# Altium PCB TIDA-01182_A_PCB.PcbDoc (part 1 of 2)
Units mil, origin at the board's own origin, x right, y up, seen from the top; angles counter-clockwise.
Board outline 4950 x 3200 mil, 4 copper layers (Component Side, Signal Layer 1, Signal Layer 2, Solder Side), stack 61.2 mil thick; 169 components, 99 nets, 868 pads, 44 vias.
Unrouted connection lines stored in the file: 4.
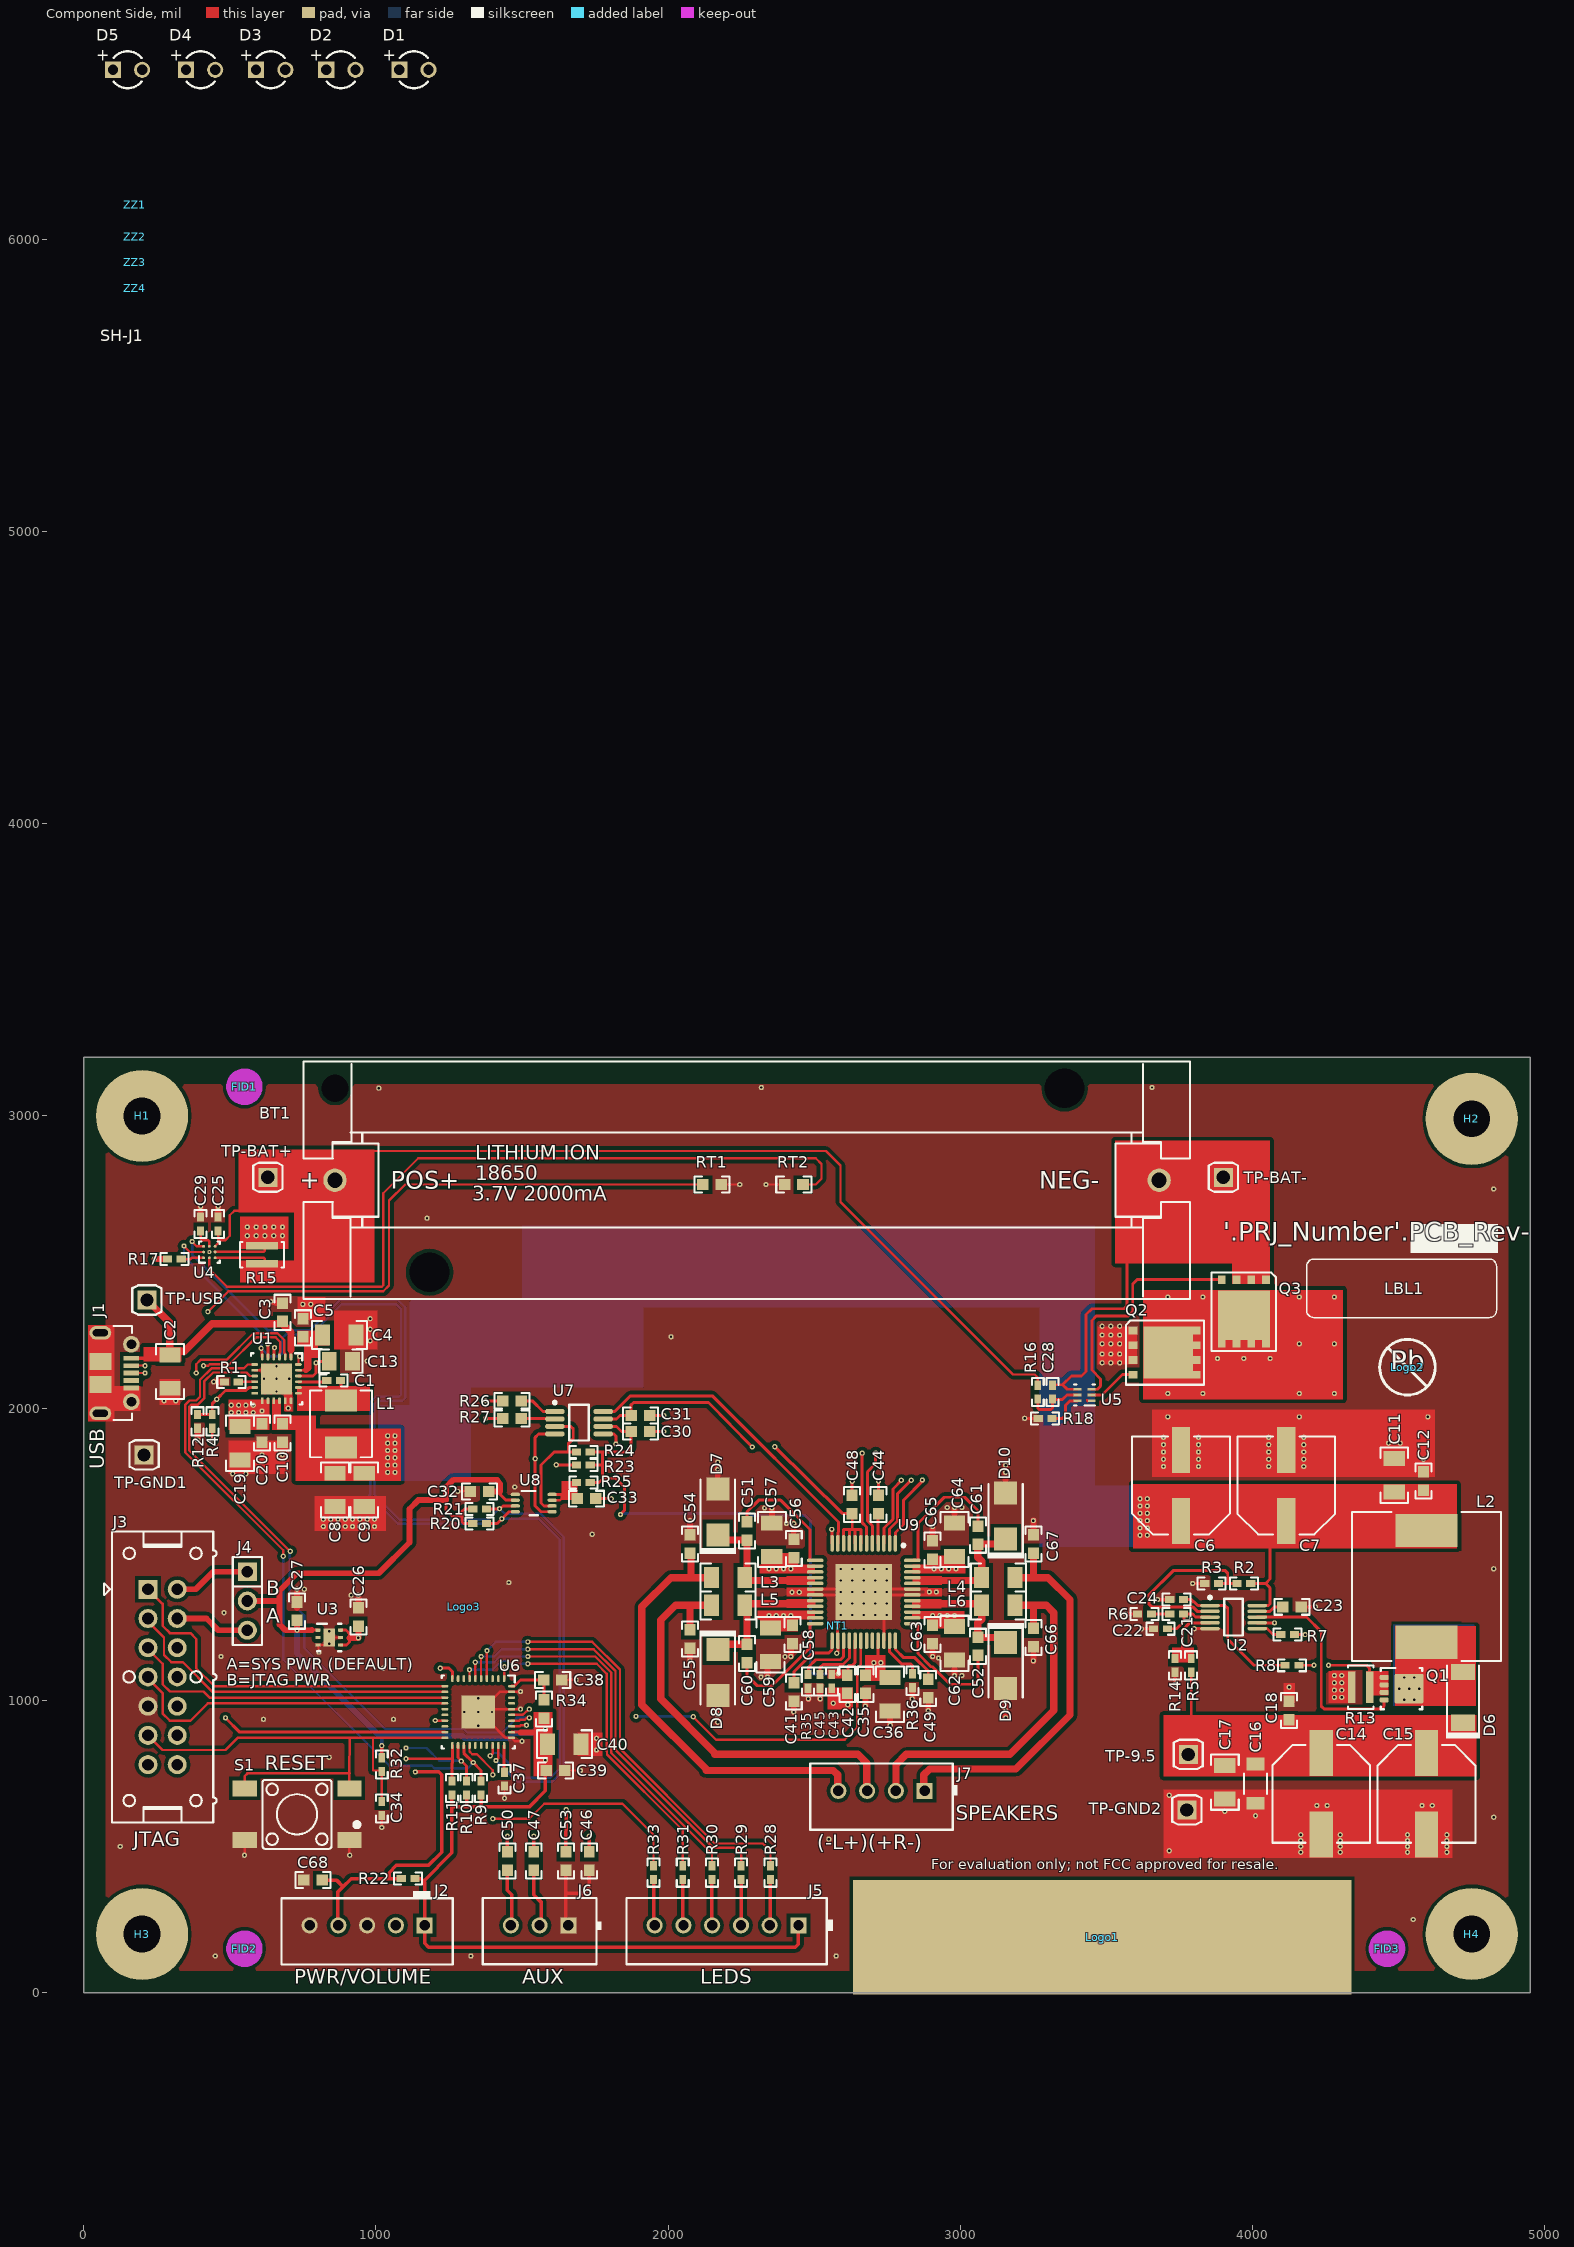
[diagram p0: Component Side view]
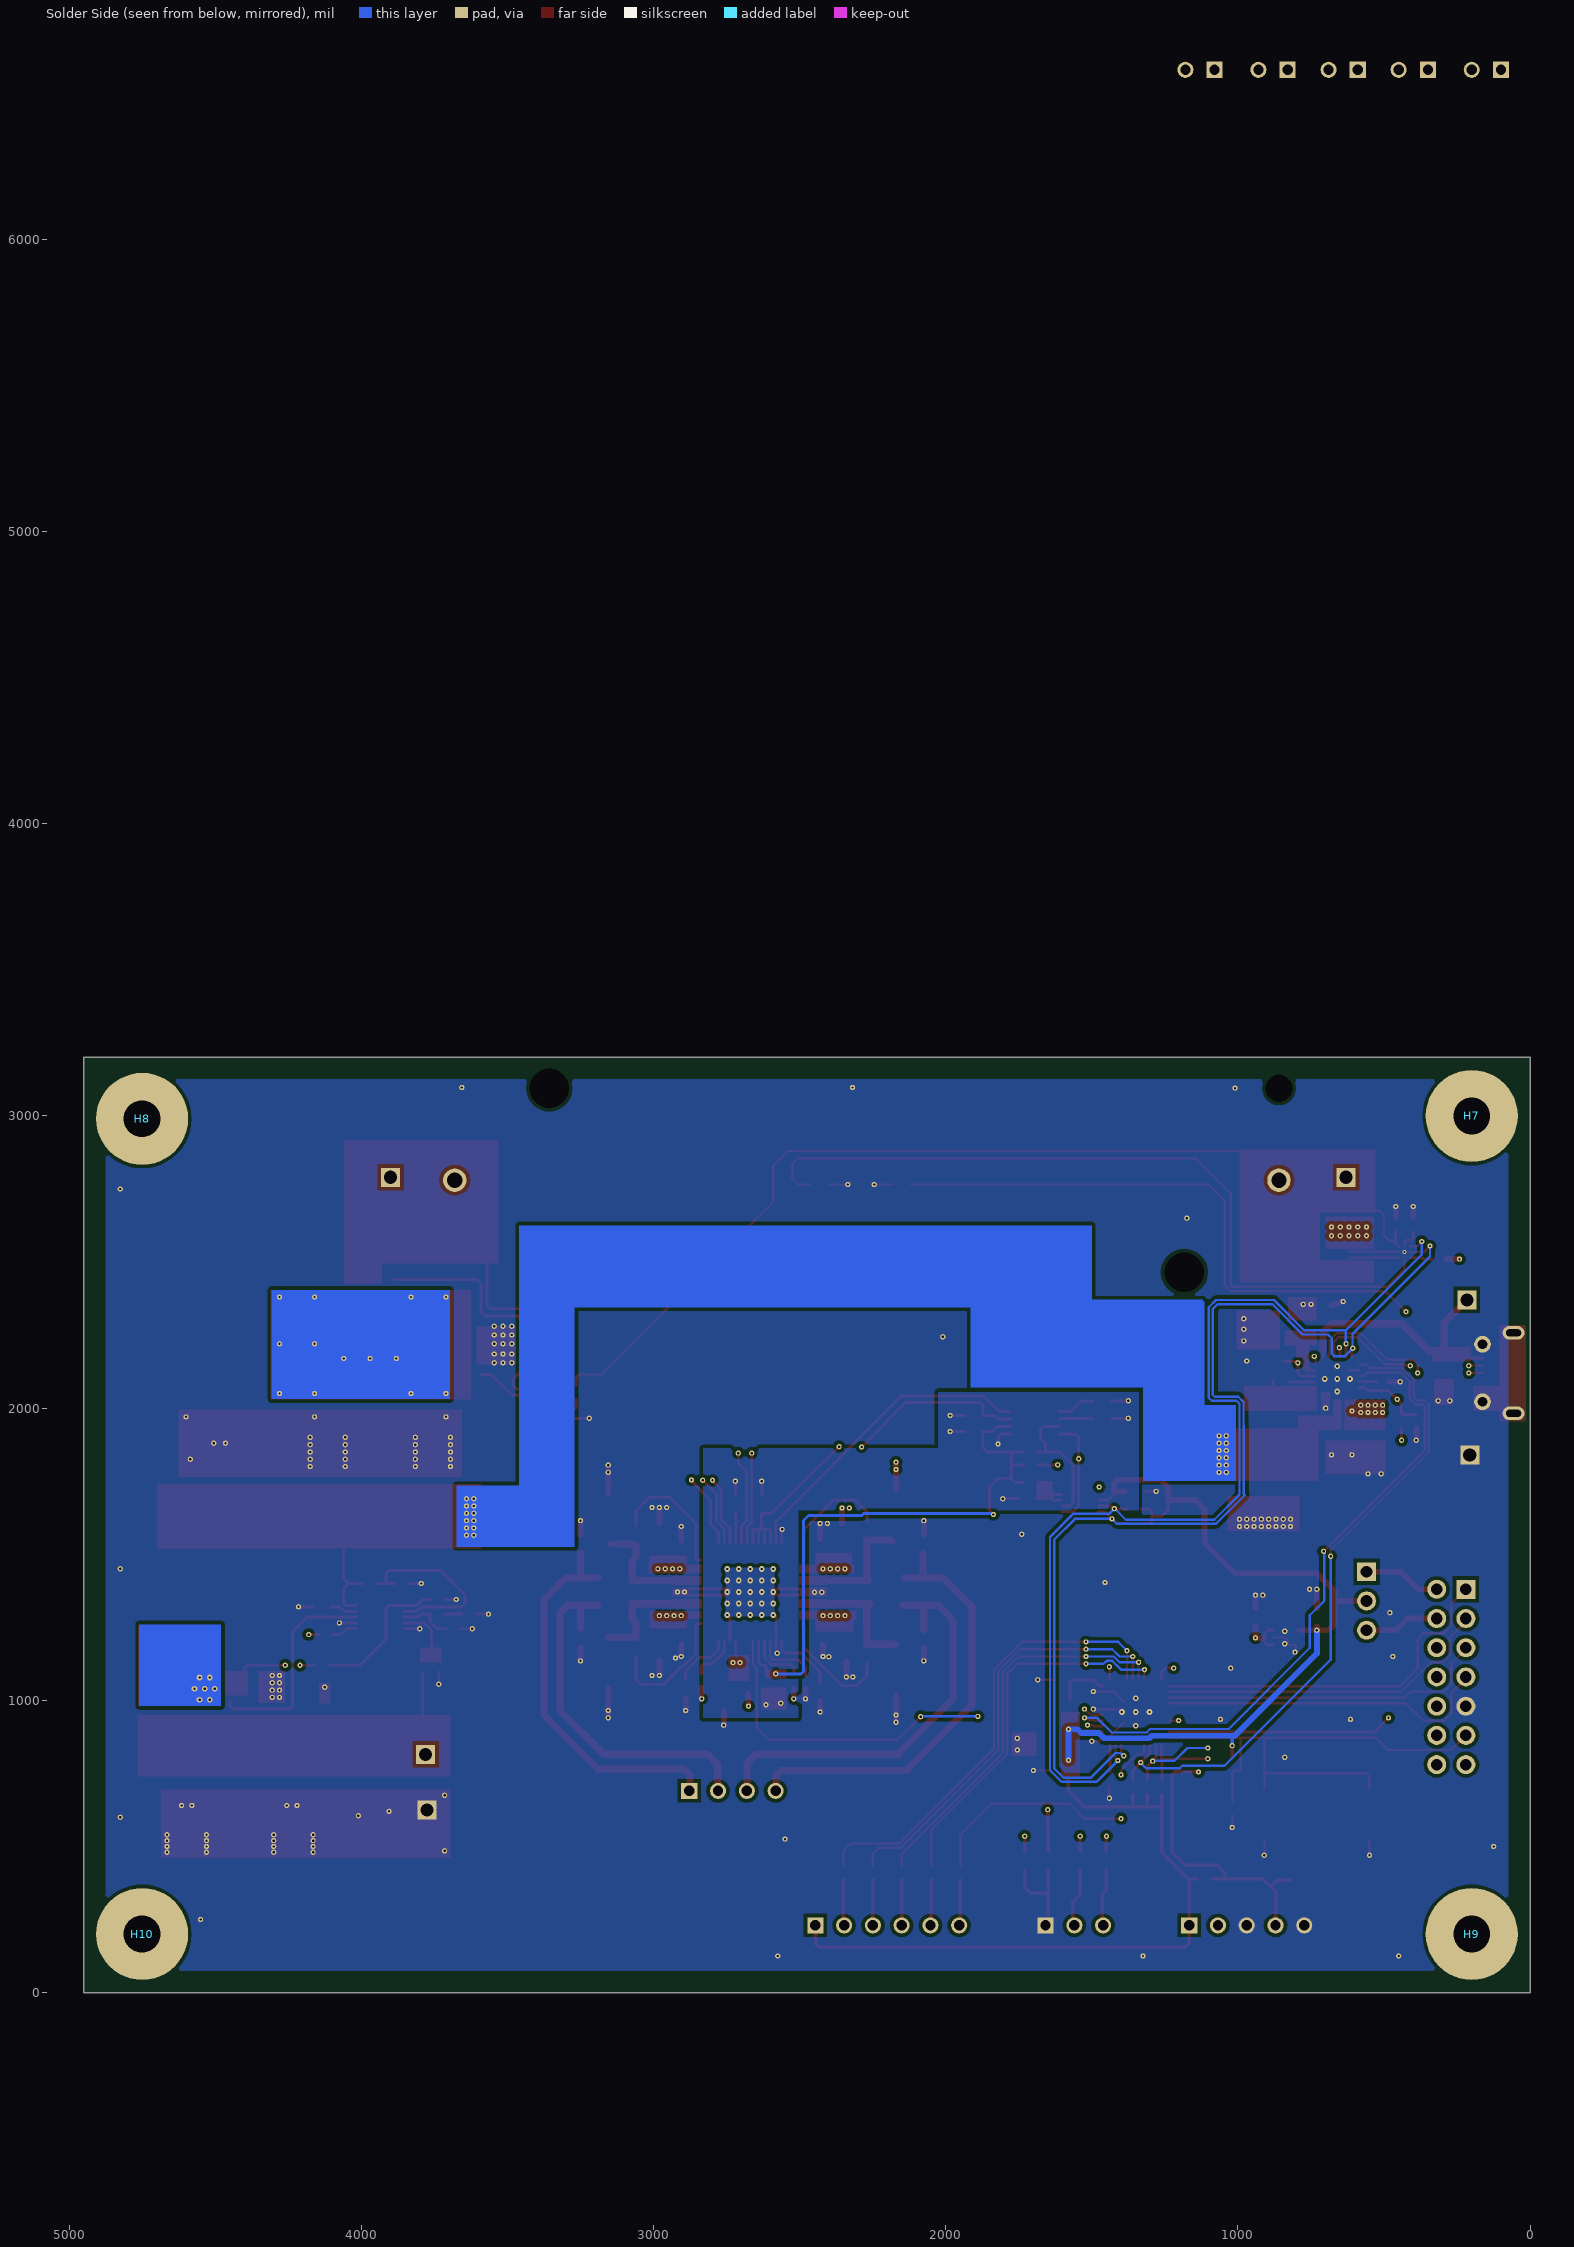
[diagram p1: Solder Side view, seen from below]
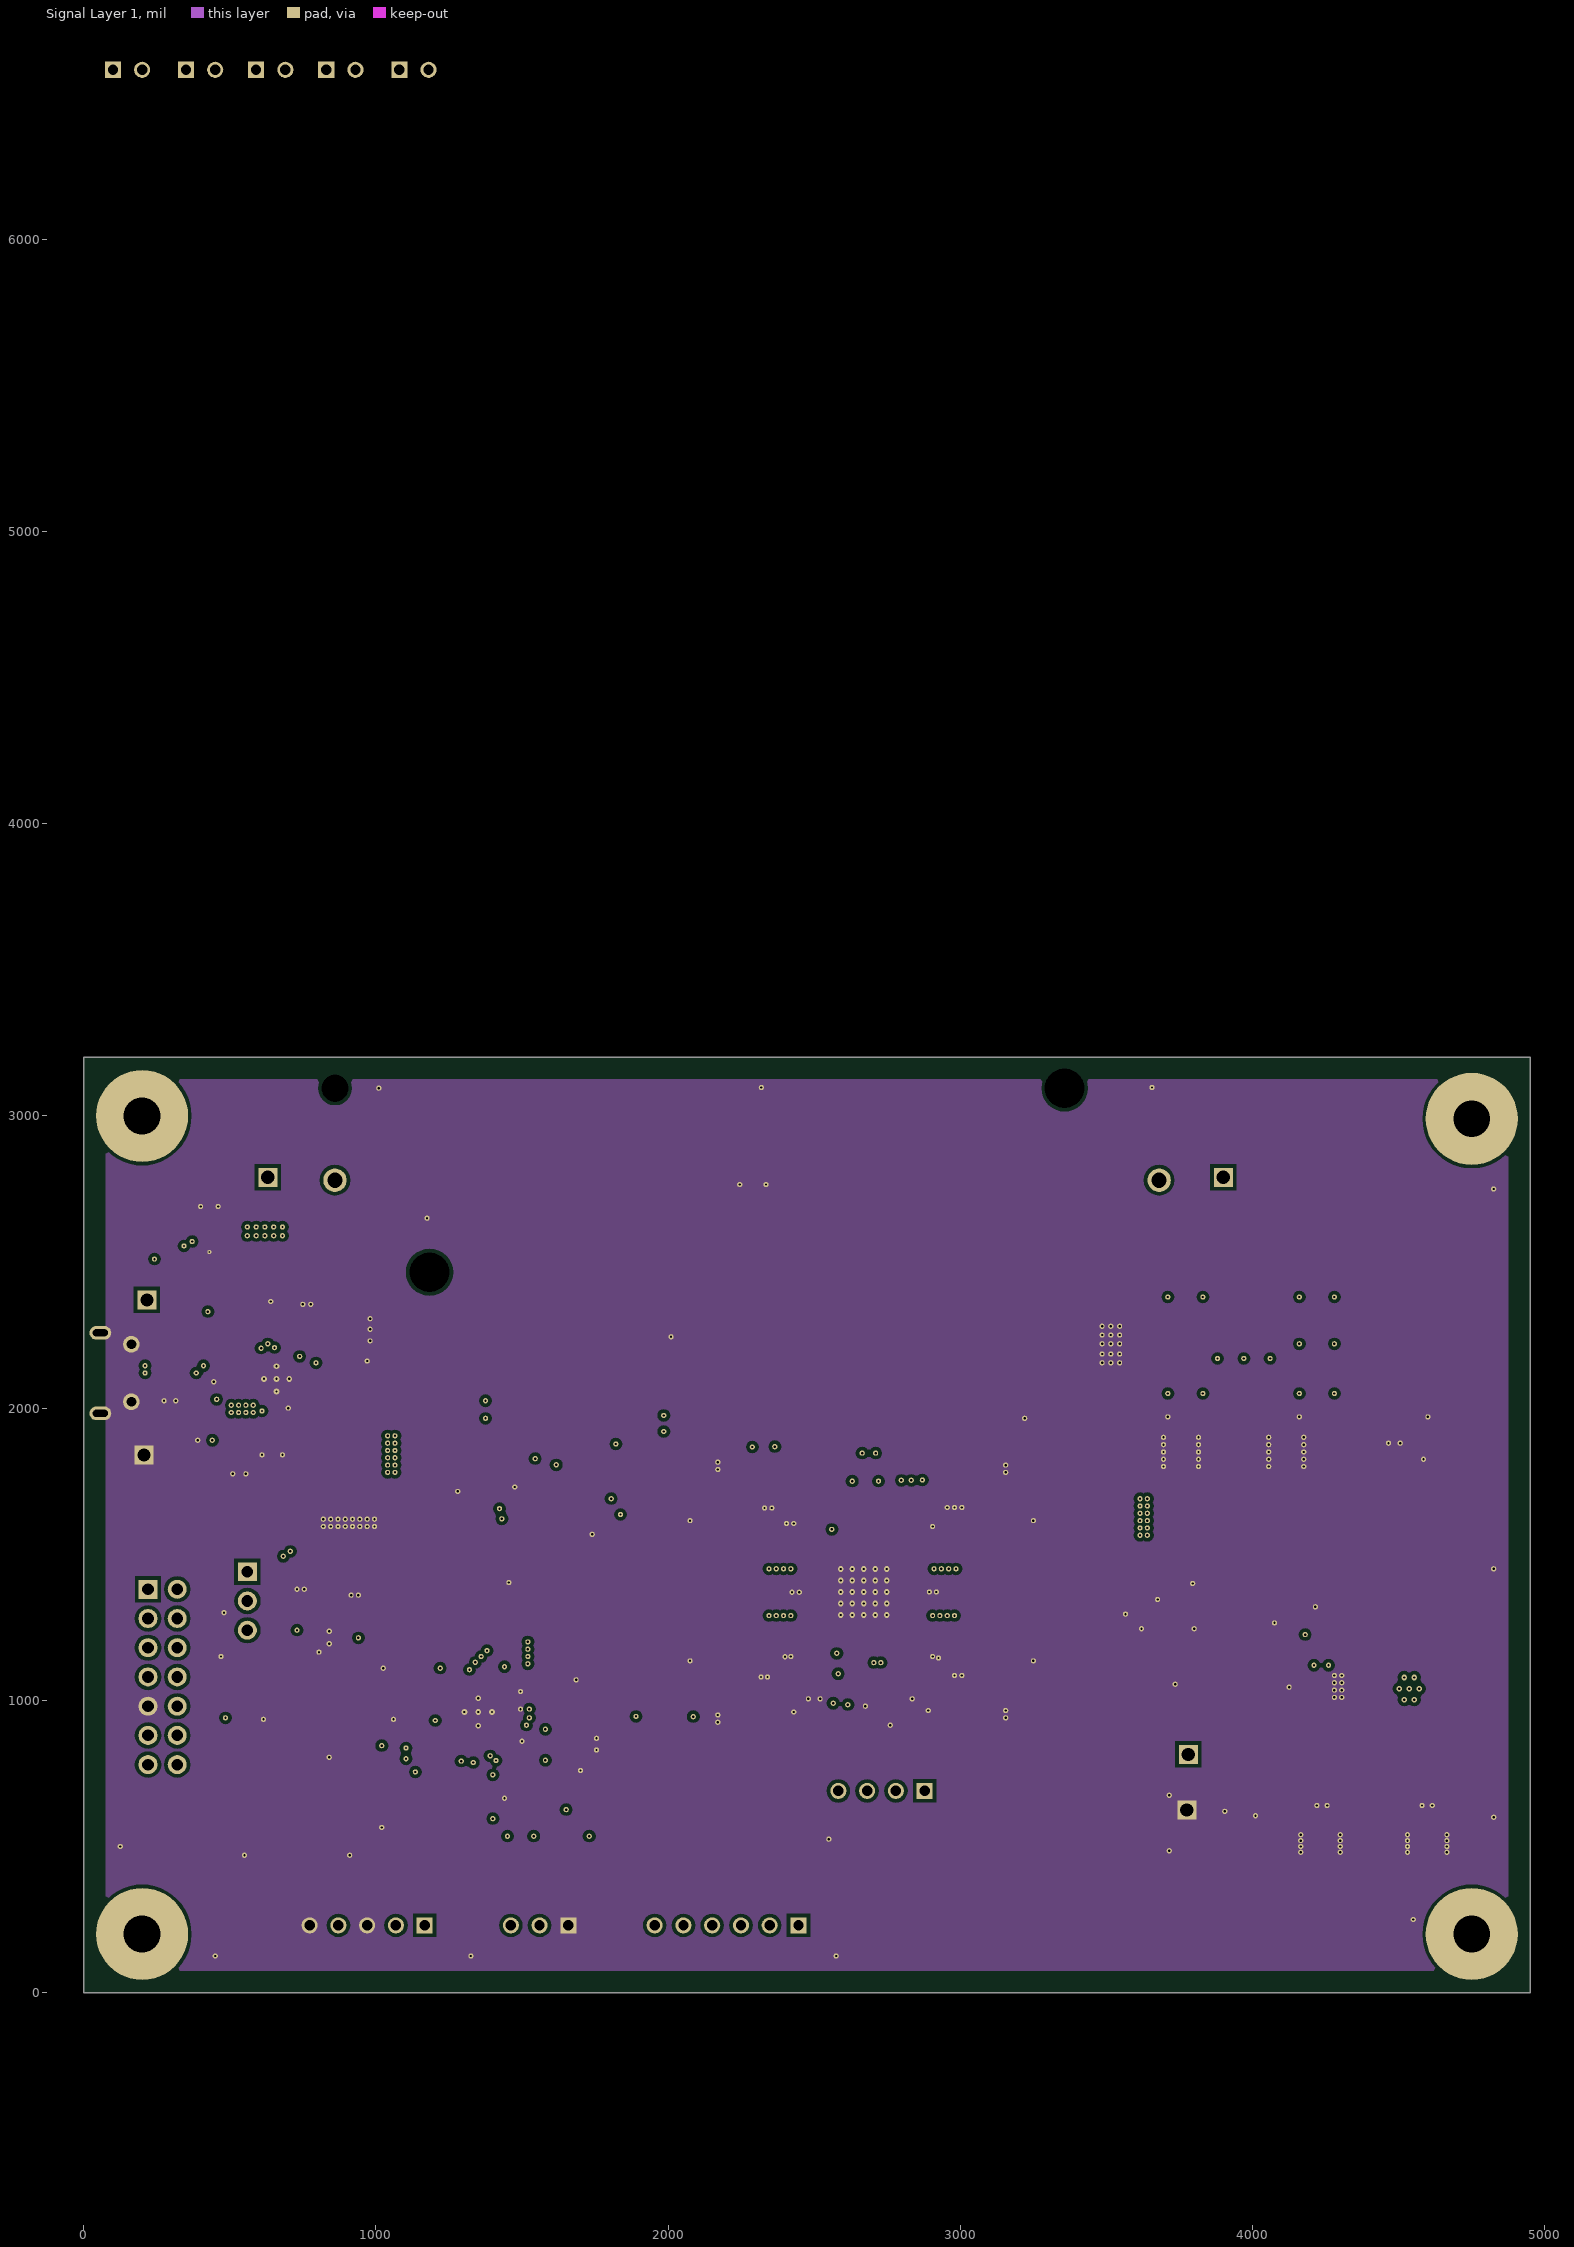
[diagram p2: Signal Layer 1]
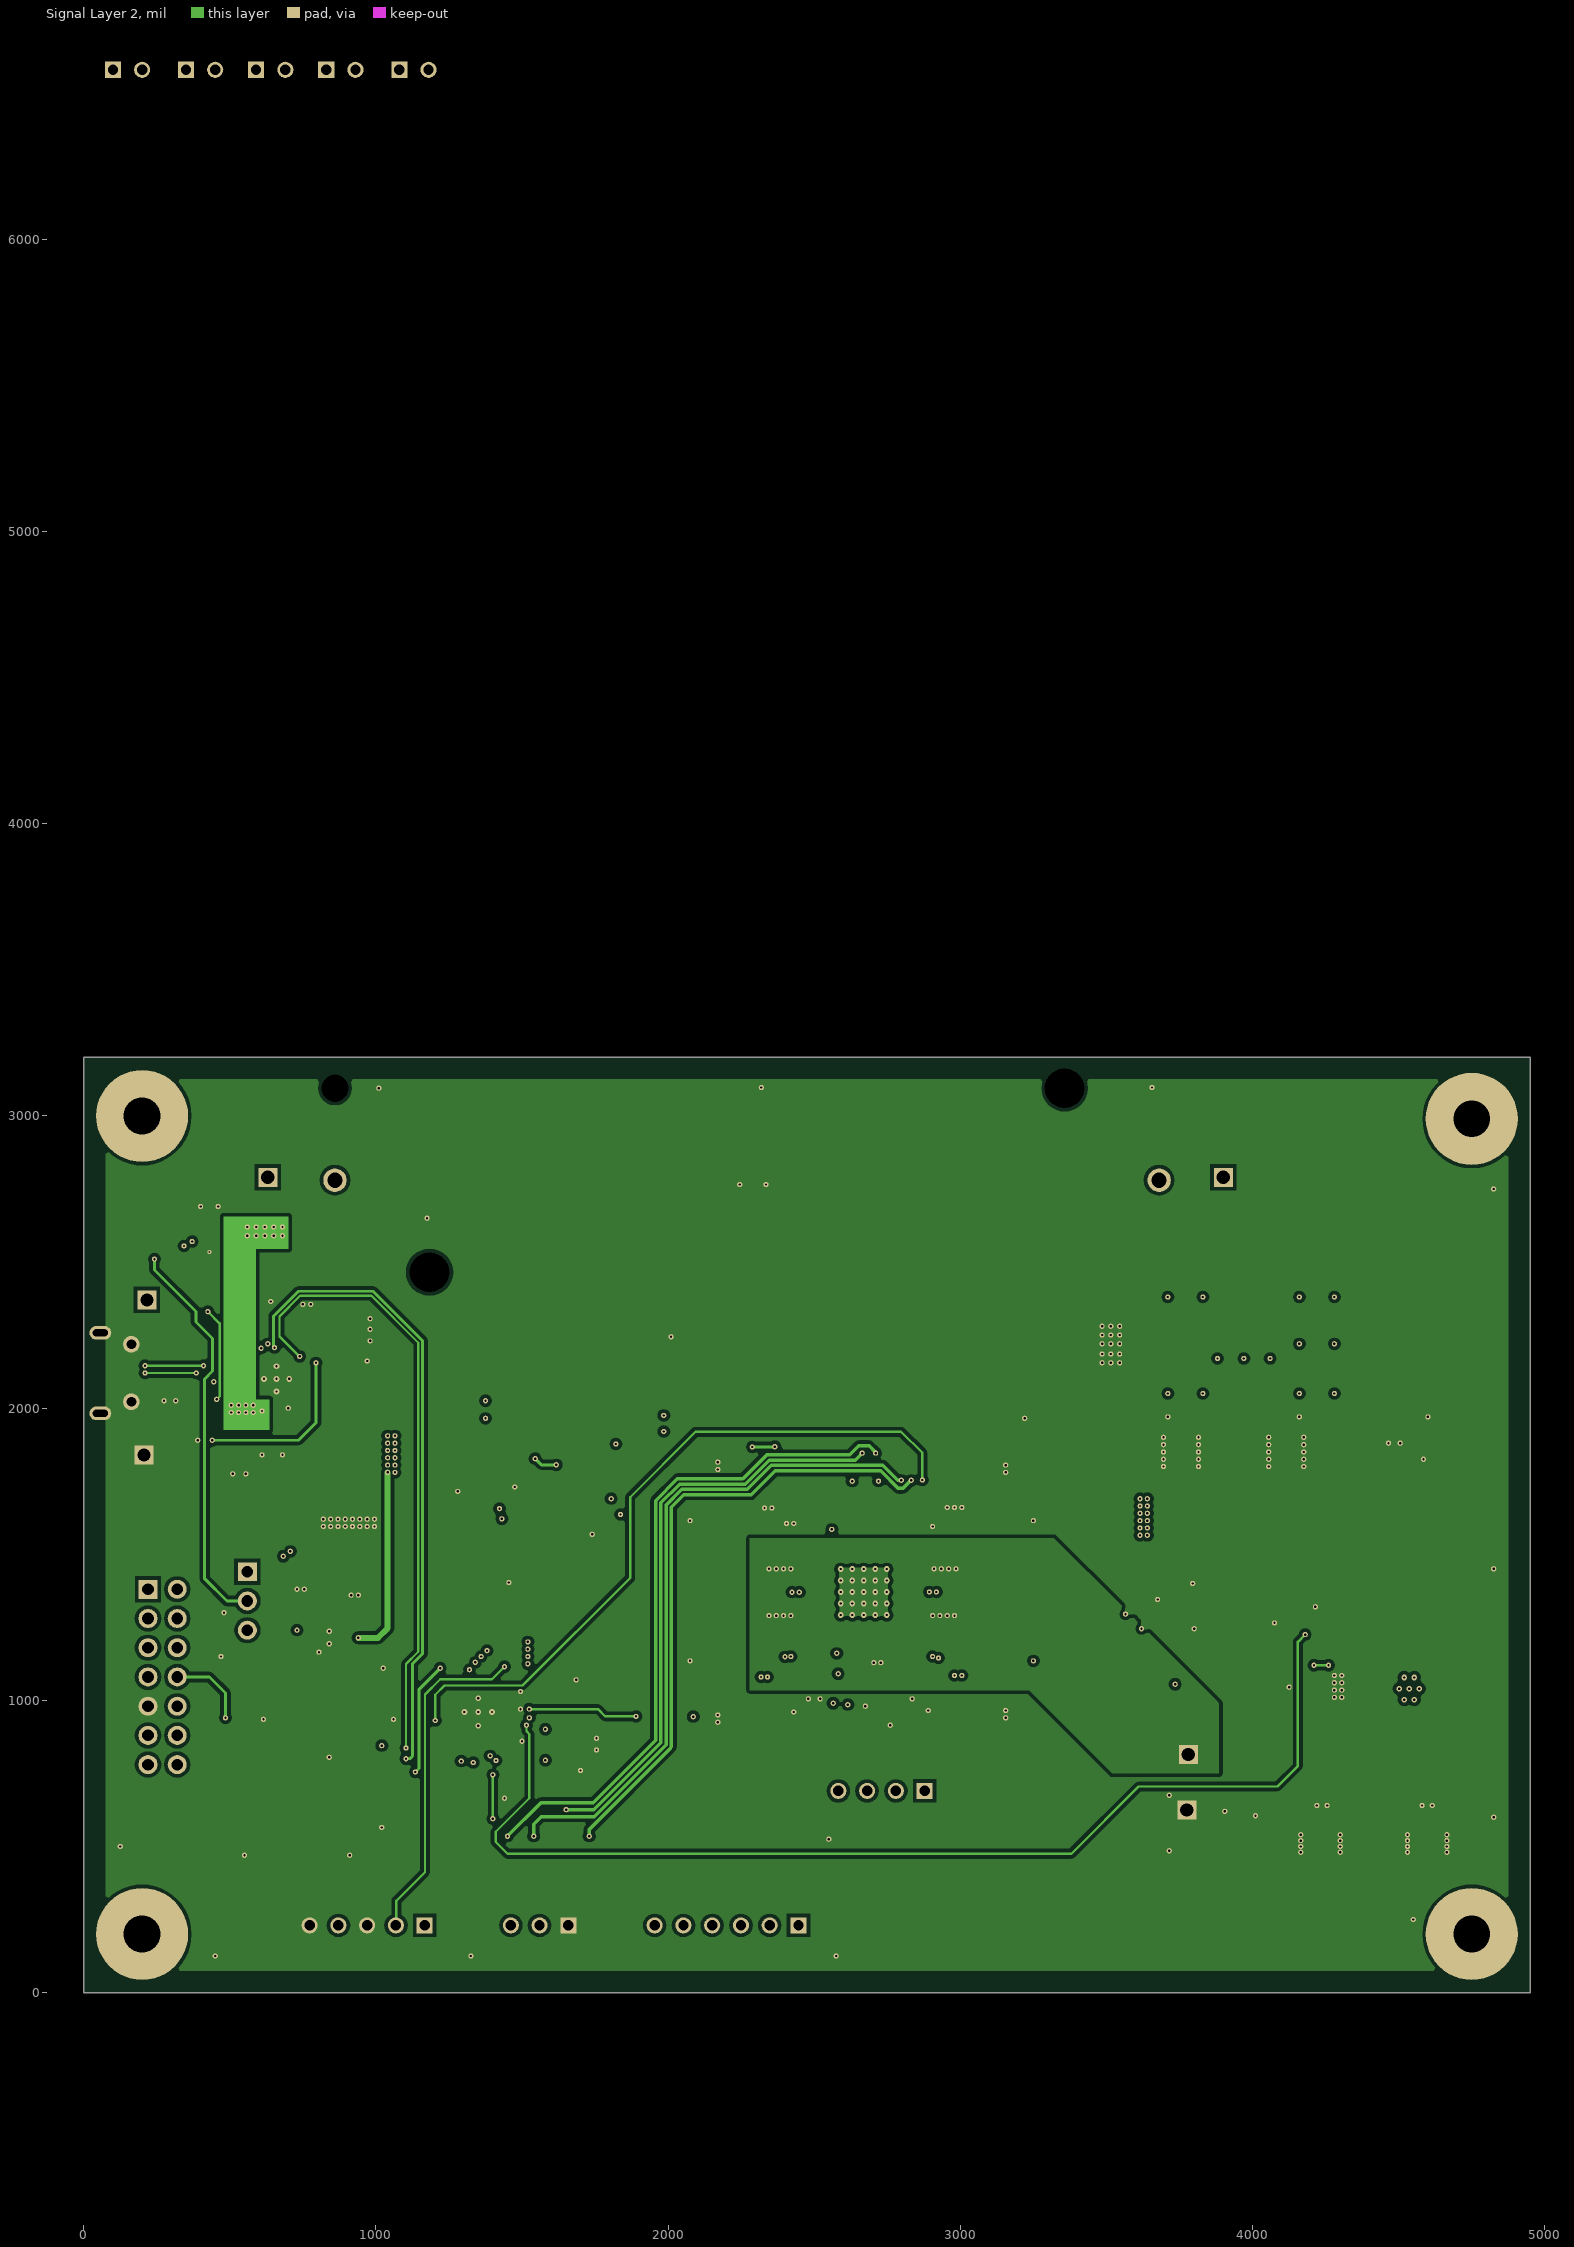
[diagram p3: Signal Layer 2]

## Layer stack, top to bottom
Top Solder: solder mask 0.4, Solder Resist, Dk 3.5
Component Side: signal copper 2.8
Dielectric 1: core 12, FR-4 High Tg, Dk 4.8
Signal Layer 1: signal copper 2.8
Dielectric 4: prepreg 26, FR-4 High Tg, Dk 4.2
Signal Layer 2: signal copper 2.8
Dielectric 3: core 12, FR-4 High Tg, Dk 4.2
Solder Side: signal copper 2.8
Bottom Solder: solder mask 0.4, Solder Resist, Dk 3.5

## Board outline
0,0 4950,0 4950,3200 0,3200

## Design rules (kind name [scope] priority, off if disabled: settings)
AcuteAngle [All] p1: minimum=4.50000000000000E+0001 checktracksonly=FALSE
AssemblyTestPointUsage [All] p1: valid=2
BoardOutlineClearance BoardOutlineClearance_MountingHoles [OnCopper and InComponentClass('Mounting Holes')] p1: gap=40
BoardOutlineClearance BoardOutlineClearance_Poly [OnCopper and InPoly] p2: gap=25
BoardOutlineClearance [OnCopper and Not InComponentClass('Logo') and not InComponentClass('FiducialMark') and not InRegion(1000,500,4000,800)] p3: gap=75
Clearance Clearance_Keepouts [((IsTrack Or IsArc) And Not InPoly) And IsFree and IsKeepOut vs ((IsTrack Or IsArc) And Not InPoly) And IsFree and IsKeepOut] p1: gap=0
Clearance Clearance_Poly [InPolygon] p2: gap=12
Clearance [All] p3: gap=6
ComponentClearance ComponentClearance_1 [InComponent('NT1') vs InComponent('U9')] p1: gap=0 collisioncheckmode=3 verticalgap=0 showdistances=FALSE
ComponentClearance ComponentClearance_MountingHoles_FiducialMarks [InComponentClass('Mounting Holes') vs InComponentClass('FiducialMark')] p2: gap=30 collisioncheckmode=3 verticalgap=10 showdistances=FALSE
ComponentClearance ComponentClearance_Shunt [InComponent('NT1') vs InComponentClass('Shunt')] p3: gap=0 collisioncheckmode=3 verticalgap=0 showdistances=FALSE
ComponentClearance ComponentClearance_Logo [InComponentClass('Logo')] p4: gap=10 collisioncheckmode=3 verticalgap=10 showdistances=FALSE
ComponentClearance ComponentClearance_ScrewToNut [(HasFootprint('NY PMS 440 0025 PH')) vs (HasFootprint('Keystone_1902C'))] p5: gap=5 collisioncheckmode=3 verticalgap=10 showdistances=FALSE
ComponentClearance ComponentClearance_MountingHoles [InComponentClass('Mounting Holes')] p6: gap=100 collisioncheckmode=3 verticalgap=100000 showdistances=FALSE
ComponentClearance ComponentClearance_SmallPassives [HasFootprint('0201*') or HasFootprint('0402*') or HasFootprint('0508') or HasFootprint('0603*') or HasFootprint('0612') or HasFootprint('0805*') or HasFootprint('0815*') or HasFootprint('0830*') or HasFootprint('1206*') or HasFootprint('1210*') or HasFootprint('1808*') or HasFootprint('1812*') or HasFootprint('1825*') or HasFootprint('2010*') or HasFootprint('2220*') or HasFootprint('2225*') or HasFootprint('2512*') or HasFootprint('2728*') or HasFootprint('3518*') vs HasFootprint('0201*') or HasFootprint('0402*') or HasFootprint('0508') or HasFootprint('0603*') or HasFootprint('0612') or HasFootprint('0805*') or HasFootprint('0815*') or HasFootprint('0830*') or HasFootprint('1206*') or HasFootprint('1210*') or HasFootprint('1808*') or HasFootprint('1812*') or HasFootprint('1825*') or HasFootprint('2010*') or HasFootprint('2220*') or HasFootprint('2225*') or HasFootprint('2512*') or HasFootprint('2728*') or HasFootprint('3518*')] p7: gap=6 collisioncheckmode=3 verticalgap=6 showdistances=FALSE
ComponentClearance ComponentClearance_THtoSMT [IsThruComponent vs IsSMTComponent] p8: gap=20 collisioncheckmode=3 verticalgap=20 showdistances=FALSE
ComponentClearance ComponentClearance_THtoTH [IsThruComponent vs IsThruComponent] p9: gap=30 collisioncheckmode=3 verticalgap=30 showdistances=FALSE
ComponentClearance [All] p10: gap=6 collisioncheckmode=3 verticalgap=10 showdistances=TRUE
DiffPairsRouting [All] p1: maxlimit=100 minlimit=10 mostfreqgap=10 toplayer_minwidth=15 toplayer_maxwidth=15 toplayer_prefwidth=15 midlayer1_minwidth=15 midlayer1_maxwidth=15 midlayer1_prefwidth=15 midlayer2_minwidth=15 midlayer2_maxwidth=15 midlayer2_prefwidth=15 bottomlayer_minwidth=15 bottomlayer_maxwidth=15 bottomlayer_prefwidth=15 maxuncoupledlength=1000
FabricationTestPointUsage TestPointUsage [All] p1: valid=2 allowmultiple=FALSE
FabricationTestpoint Testpoint [All] p1: side=3 testpointundercomponent=TRUE minsize=40 maxsize=100 preferedsize=60 minholesize=0 maxholesize=40 preferedholesize=32 testpointgrid=1 allowsidetop=TRUE allowsidebottom=TRUE usegrid=TRUE gridtolerance=0.01
FanoutControl Fanout_LCC [IsLCC] p1: bgadir=Out bgaviamode=Centered fanoutstyle=Auto fanoutdirection=Alternating viagrid=1 // Fanout_LCC (Default Rule)
FanoutControl Fanout_BGA [IsBGA] p2: bgadir=Out bgaviamode=Centered fanoutstyle=Auto fanoutdirection=Alternating viagrid=1 // Fanout_BGA (Default Rule)
FanoutControl Fanout_Default [All] p4: bgadir=Out bgaviamode=Centered fanoutstyle=Auto fanoutdirection=Alternating viagrid=1 // Fanout_Default (Default Rule)
FanoutControl Fanout_Small [(CompPinCount < 5)] p5: bgadir=Out bgaviamode=Centered fanoutstyle=Auto fanoutdirection=OutThenIn viagrid=1 // Fanout_Small (Default Rule)
HoleSize [All] p1: absolutevalues=TRUE maxlimit=251 minlimit=6 maxpercent=80.000 minpercent=20.000
MinimumAnnularRing MinimumAnnularRing_ThermalPadVias [IsVia and InAnyComponent] p1: minimumring=4
MinimumAnnularRing [All] p2: minimumring=4
MinimumSolderMaskSliver MinimumSolderMaskSliver_Logo [InComponentClass('Logo') vs InComponentClass('Logo')] p1: minsoldermaskwidth=0.7
MinimumSolderMaskSliver [All] p2: minsoldermaskwidth=3
PlaneClearance [All] p1: clearance=12
PlaneConnect [All] p1: planeconnectstyle=Direct reliefexpansion=10 reliefentries=4 reliefconductorwidth=10 reliefairgap=10
PolygonConnect [All] p1: connectstyle=Direct reliefconductorwidth=10 reliefentries=4 polygonreliefangle="90 Angle" airgapwidth=10
RoutingVias ThermalPadVias [IsVia and InAnyComponent] p1: holewidth=7.87 width=19.68 viastyle="Through Hole" minholewidth=7.87 minwidth=19.68 maxholewidth=12.99 maxwidth=23.62
RoutingVias [All] p2: holewidth=16 width=34 viastyle="Through Hole" minholewidth=7.87 minwidth=18 maxholewidth=40 maxwidth=65
SilkToBoardRegionClearance [Not ((IsComment or IsDesignator) And (Hide <> 'False')) and not InRegion(1000,500,4000,800)] p1:
SilkToSilkClearance SilkToSilkClearance_Pb-FreeLogo [(HasFootprint('Pb-Free_Overlay_Medium') OR HasFootprint('Pb-Free_Overlay_Small')) vs (HasFootprint('Pb-Free_Overlay_Medium') OR HasFootprint('Pb-Free_Overlay_Small'))] p1: silktosilkclearance=0
SilkToSilkClearance [All] p2: silktosilkclearance=4
SilkToSolderMaskClearance SilkToComponentPadClearance [IsPad and InAnycomponent] p1: minsilkscreentomaskgap=4 clearancetoexposedcopper=TRUE
SilkToSolderMaskClearance "Silk to Solder Mask Opening" [All] p2: minsilkscreentomaskgap=3 clearancetoexposedcopper=FALSE
SolderMaskExpansion [All] p1: expansion=1.97
Width [All] p1: maxlimit=100 minlimit=6 preferedwidth=10 checkconnectedcopper=TRUE
14 further rules are at their usual default settings.

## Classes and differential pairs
component class TIDA-01182_A_SCH_2: C30 C31 C32 C33 C34 C35 C36 C37 C38 C39 C40 C41 C42 C43 C44 C45 C46 C47 C48 C49 C50 C51 C52 C53 C54 C55 C56 C57 C58 C59 C60 C61 C62 C63 C64 C65 C66 C67 C68 D7 D8 D9 D10 J2 J3 J4 J5 J6 J7 L3 L4 L5 L6 NT1 R20 R21 R22 R23 R24 R25 R26 R27 R28 R29 R30 R31 R32 R33 R34 R35 R36 S1 U6 U7 U8 U9
component class TIDA-01182_A_SCH_1: BT1 C1 C2 C3 C4 C5 C6 C7 C8 C9 C10 C11 C12 C13 C14 C15 C16 C17 C18 C19 C20 C21 C22 C23 C24 C25 C26 C27 C28 C29 D6 J1 L1 L2 Q1 Q2 Q3 R1 R2 R3 R4 R5 R6 R7 R8 R9 R10 R11 R12 R13 R14 R15 R16 R17 R18 RT1 RT2 TP-9.5 TP-BAT+ TP-BAT- TP-GND1 TP-GND2 TP-USB U1 U2 U3 U4 U5
component class Header: J4 TP-9.5 TP-BAT+ TP-BAT- TP-GND1 TP-GND2 TP-USB
component class "Mounting Holes": H1 H2 H3 H4
component class Logo: Logo1
component class TIDA-01182_A_EVM_Hardware: D1 D2 D3 D4 D5 FID1 FID2 FID3 H1 H2 H3 H4 H7 H8 H9 H10 LBL1 Logo1 Logo2 Logo3 SH-J1 ZZ1 ZZ2 ZZ3 ZZ4
component class FiducialMark: FID1 FID2 FID3
component class AssemblyNote: ZZ1 ZZ2 ZZ3 ZZ4
component class Label: LBL1
component class Shunt: SH-J1

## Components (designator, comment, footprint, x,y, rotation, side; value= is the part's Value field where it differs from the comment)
BT1 "1043" BAT_1043 2270,2780 r0 top
C1 "GRM155R71E473KA88D" 0402 855,2095 r180 top
C2 "885012208069" 1206 295,2125 r270 top
C3 "885012206071" 0603 680,2328 r90 top
C4 "885012208069" 1206 875,2250 r0 top
C5 "885012206071" 0603 750,2275 r90 top
C6 "EEE-FK1E101P" SM_RADIAL_E 3755,1735 r90 top
C7 "EEE-FK1E101P" SM_RADIAL_E 4115,1735 r90 top
C8 "885012208069" 1206 860,1720 r270 top
C9 "885012208069" 1206 960,1720 r270 top
C10 "885012206071" 0603 680,1915 r270 top
C11 "885012208069" 1206 4485,1770 r90 top
C12 "885012206071" 0603 4585,1750 r90 top
C13 "885012207025" 0805_HV 880,2160 r0 top
C14 "EEE-FC1E680P" SM_RADIAL_F 4235,680 r270 top
C15 "EEE-FC1E680P" SM_RADIAL_F 4595,680 r270 top
C16 "C3216X5R1E336M160AC" 1206_180 4010,715 r270 top
C17 "885012208069" 1206 3905,720 r270 top
C18 "885012206071" 0603 4125,965 r90 top
C19 "885012208069" 1206 535,1880 r270 top
C20 "885012206071" 0603 610,1915 r270 top
C21 "C1005X7R1H473K050BB" 0402 3740,1295 r180 top
C22 "GRM155R71H272KA01D" 0402 3685,1245 r180 top
C23 "GRM188R71C474KA88D" 0603 4135,1320 r0 top
C24 "885012205031" 0402 3740,1345 r180 top
C25 "GRM155R61A105KE15D" 0402 460,2630 r90 top
C26 "C0603C105K3RACTU" 0603 940,1285 r90 top
C27 "C0603C105K3RACTU" 0603 730,1305 r90 top
C28 "GRM155R71A104KA01D" 0402 3314.88,2054.74 r90 top
C29 "GRM155R61C225KE11D" 0402 400,2630 r90 top
C30 "885012206071" 0603 1905,1920 r0 top
C31 "885012206071" 0603 1905,1975 r0 top
C32 "885012206071" 0603 1355,1715 r180 top
C33 "885012206071" 0603 1720,1690 r0 top
C34 "GRM155R61C225KE11D" 0402 1020,630 r270 top
C35 "885012206071" 0603 2676,1055 r270 top
C36 "885012208069" 1206 2759.37,1020.63 r270 top
C37 "GRM155R71H472KA01D" 0402 1440,730 r270 top
C38 "885012206071" 0603 1605,1070 r0 top
C39 "885012206071" 0603 1615,760 r0 top
C40 "885012208069" 1206 1645,850 r0 top
C41 "GRM188R71C105KA12D" 0603 2430,1028 r90 top
C42 "885012206071" 0603 2613,1055 r270 top
C43 "GRM155R61C225KE11D" 0402 2560,1065 r270 top
C44 "GRM188R71C105KA12D" 0603 2719.37,1670.63 r90 top
C45 "885012005063" 0402 2519,1065 r270 top
C46 "GRM188R71C105KA12D" 0603 1730,450 r270 top
C47 "GRM188R71C105KA12D" 0603 1540,450 r270 top
C48 "885012206071" 0603 2629.37,1670.63 r90 top
C49 "GRM188R71C105KA12D" 0603 2890,1040 r90 top
C50 "GRM188R71C105KA12D" 0603 1450,450 r270 top
C51 "C0603C103K5RACTU" 0603 2270,1580 r90 top
C52 "C0603C103K5RACTU" 0603 3060,1185 r90 top
C53 "GRM188R71C105KA12D" 0603 1650,450 r270 top
C54 "C0603C102K5RACTU" 0603 2075,1535 r90 top
C55 "C0603C102K5RACTU" 0603 2075,1210 r270 top
C56 "885012206071" 0603 2430,1520 r90 top
C57 "885012208069" 1206 2355,1550 r90 top
C58 "885012206071" 0603 2425,1225 r270 top
C59 "885012208069" 1206 2350,1190 r270 top
C60 "C0603C103K5RACTU" 0603 2270,1160 r270 top
C61 "C0603C103K5RACTU" 0603 3060,1565 r270 top
C62 "885012208069" 1206 2980,1195 r270 top
C63 "885012206071" 0603 2905,1225 r270 top
C64 "885012208069" 1206 2980,1550 r90 top
C65 "885012206071" 0603 2905,1515 r90 top
C66 "C0603C102K5RACTU" 0603 3250,1215 r270 top
C67 "C0603C102K5RACTU" 0603 3250,1535 r90 top
C68 "885012206071" 0603 785,385 r180 top
D1 "WP710A10LVBC/D" WP710A10_Blue 1130,6580 r0 top
D2 "WP710A10LVBC/D" WP710A10_Blue 880,6580 r0 top
D3 "WP710A10LVBC/D" WP710A10_Blue 640,6580 r0 top
D4 "WP710A10LVBC/D" WP710A10_Blue 400,6580 r0 top
D5 "WP710A10LVBC/D" WP710A10_Blue 150,6580 r0 top
D6 "CMS06" M-FLAT 4720,1010 r90 top
D7 "B130-13-F" SMA 2170,1645 r90 top
D8 "B130-13-F" SMA 2170,1095 r270 top
D9 "B130-13-F" SMA 3155,1120 r270 top
D10 "B130-13-F" SMA 3155,1630 r90 top
FID1 "Fiducial" Fiducial10-30 550,3100 r0 top
FID2 "Fiducial" Fiducial10-30 550,150 r0 top
FID3 "Fiducial" Fiducial10-30 4460,150 r0 top
H1 "NY PMS 440 0025 PH" "NY PMS 440 0025 PH" 200,3000 r0 top locked
H2 "NY PMS 440 0025 PH" "NY PMS 440 0025 PH" 4750,2990 r0 top locked
H3 "NY PMS 440 0025 PH" "NY PMS 440 0025 PH" 200,200 r0 top locked
H4 "NY PMS 440 0025 PH" "NY PMS 440 0025 PH" 4750,200 r0 top locked
H7 "1902C" Keystone_1902C 200,3000 r180 bottom locked
H8 "1902C" Keystone_1902C 4750,2990 r180 bottom locked
H9 "1902C" Keystone_1902C 200,200 r180 bottom locked
H10 "1902C" Keystone_1902C 4750,200 r180 bottom locked
J1 "105017-0001" CONN_105017-0001 110,2120 r270 top
J2 "B5B-XH-A(LF)(SN)" JST_B5B-XH-A 970,230 r180 top
J3 "SBH11-PBPC-D07-ST-BK" CONN_SBH11-PBPC-D07-ST-BK 270,1080 r270 top
J4 "PBC03SAAN" PBC03SAAN 560,1340 r270 top
J5 "B6B-XH-A(LF)(SN)" JST_B6B-XH-A 2200,230 r180 top
J6 "B3B-XH-A(LF)(SN)" JST_B3B-XH-A 1560,230 r180 top
J7 "B4B-XH-A(LF)(SN)" JST_B4B-XH-A 2730,690 r180 top
L1 "IHLP2020BZER1R0M11" IHLP-2020BZ 881,1946 r270 top
L2 "SRR1280-4R7Y" SRR1280 4595,1390 r270 top
L3 "2512067007Y3" 1206 2205,1420 r0 top
L4 "2512067007Y3" 1206 3130,1420 r0 top
L5 "2512067007Y3" 1206 2205,1325 r0 top
L6 "2512067007Y3" 1206 3130,1325 r0 top
LBL1 "Size: 0.65\" x 0.20 \"" Label_650x200 4510,2410 r0 top
Logo1 "Texas Instruments" TI_Stacked_SolderMask_Medium 3485,190 r0 top
Logo2 "Pb-Free Symbol" Pb-Free_Overlay_Medium 4530,2140 r0 top
Logo3 "FCC disclaimer" FCC_disclaimer 1300,1320 r0 top
NT1 "Net-Tie" Net-Tie_10mil 2580,1255 r270 top net-tie
Q1 "CSD16323Q3" DQG0008A 4510,1040 r0 top
Q2 "CSD17578Q5A" TRANS_NexFET_Q5A 3700,2190 r0 top
Q3 "CSD17578Q5A" TRANS_NexFET_Q5A 3970,2330 r270 top
R1 "CRCW0402196RFKED" 0402 505,2090 r180 top
R2 "CRCW040241K2FKED" 0402 3970,1400 r0 top
R3 "CRCW040245K3FKED" 0402 3860,1400 r0 top
R4 "CRCW04025K23FKED" 0402 440,1955 r270 top
R5 "CRCW04026K49FKED" 0402 3790,1120 r270 top
R6 "CRCW04022K87FKED" 0402 3630,1295 r0 top
R7 "CRCW040261K9FKED" 0402 4120,1225 r180 top
R8 "CRCW0402100RFKED" 0402 4135,1120 r0 top
R9 "CRCW040210K0FKED" 0402 1360,700 r270 top
R10 "CRCW040210K0FKED" 0402 1310,700 r270 top
R11 "CRCW040210K0FKED" 0402 1260,700 r270 top
R12 "CRCW040230K1FKED" 0402 390,1955 r90 top
R13 "PRL1632-R009-F-T1" 0612 4370,1045 r0 top
R14 "CRCW04021K00FKED" 0402 3735,1120 r90 top
R15 "PRL1632-R010-F-T1" 0612 610,2525 r270 top
R16 "CRCW0402221RFKED" 0402 3264.88,2054.74 r90 top
R17 "CRCW040210K0FKED" 0402 310,2510 r180 top
R18 "CRCW04022K21FKED" 0402 3290,1965 r0 top
R20 "CRCW04022K20FKED" 0402 1355,1605 r180 top
R21 "CRCW04022K20FKED" 0402 1355,1655 r180 top
R22 "CRCW040210K0FKED" 0402 1110,390 r0 top
R23 "ERJ-2RKF4701X" 0402 1710,1805 r0 top
R24 "ERJ-2RKF4701X" 0402 1710,1850 r0 top
R25 "CRCW0402200KFKED" 0402 1710,1745 r180 top
R26 "ERJ-3GEY0R00V" 0603 1465,2025 r0 top
R27 "ERJ-3GEY0R00V" 0603 1465,1965 r0 top
R28 "CRCW040210R0FKED" 0402 2350,410 r90 top
R29 "CRCW040210R0FKED" 0402 2250,410 r90 top
R30 "CRCW040210R0FKED" 0402 2150,410 r90 top
R31 "CRCW040210R0FKED" 0402 2050,410 r90 top
R32 "CRCW040247K5FKED" 0402 1020,780 r90 top
R33 "CRCW040210R0FKED" 0402 1950,410 r90 top
R34 "CRCW06033R01FKEA" 0603 1575,970 r270 top
R35 "CRCW0402120RJNED" 0402 2478,1065 r270 top
R36 "CRCW0402120KFKED" 0402 2836,1067 r270 top
RT1 "ERT-J1VG103FA" 0603 2150,2765 r180 top
RT2 "ERT-J1VG103FA" 0603 2430,2765 r0 top
S1 "4-1437565-1" SW_FSM4JSMA 730,610 r270 top
SH-J1 "969102-0000-DA" SNT-100-BK-G 100,5525 r90 top
TP-9.5 "61300111121" WURTH_61300111121 3780,815 r90 top
TP-BAT+ "61300111121" WURTH_61300111121 630,2790 r90 top
TP-BAT- "61300111121" WURTH_61300111121 3900,2790 r90 top
TP-GND1 "61300111121" WURTH_61300111121 206.48,1840 r90 top
TP-GND2 "61300111121" WURTH_61300111121 3775,625 r90 top
TP-USB "61300111121" WURTH_61300111121 216.48,2370 r90 top
U1 "BQ25895RTWR" RTW0024H 660,2100 r270 top
U2 "LM3481MM" MUB10A_N 3935,1285 r0 top
U3 "TPS78225QDRVRQ1" DRV0006A 840,1215 r0 top
U4 "BQ27426YZFR" YZF0009-C01 430,2534 r90 top
U5 "BQ29705DSER" DSE0006A 3424.88,2044.74 r180 top
U6 "MSP430FR5735IRHAR" RHA0040D 1350,960 r270 top
U7 "DAC081C085CIMM/NOPB" MUA08A_N 1695,1950 r0 top
U8 "PCA9306DCUR" DCU0008A_N 1540,1675 r0 top
U9 "TPA3004D2PHPR" PHP0048D_N 2669.37,1370.63 r270 top
ZZ1 "This Assembly Note is for PCB labels only" AssemblyNoteLabel 175,6118 r0 top
ZZ2 "This Assembly Note will show in the PcbDoc and associated outputs" AssemblyNote 175,6009.11 r0 top
ZZ3 "Three different wire assemblies to be supplied with each board" AssemblyNote 175,5920.56 r0 top
ZZ4 "Place the shunt on J4 position A" AssemblyNote 175,5832 r0 top

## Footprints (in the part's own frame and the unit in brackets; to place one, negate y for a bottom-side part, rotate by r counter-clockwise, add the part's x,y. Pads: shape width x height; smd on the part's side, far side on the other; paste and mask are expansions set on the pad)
0402 [mm] "0402 from SM-752 data"
  rect 0.8x0.6 smd: 1(-0.6,0) 2(0.6,0)
  silkscreen extent -1.22,-0.52 1.22,0.52, body extent -0.55,-0.3 0.55,0.3, height 0.6
0603 [mm] "0603 from SM-752 data"
  rect 1x0.95 smd: 1(-0.8,0) 2(0.8,0)
  silkscreen extent -1.52,-0.69 1.52,0.69, body extent -0.87,-0.47 0.87,0.47, height 1
0612 [mm] "Panasonic recommended land pattern, fb97d03ed01.pdf dated April 2008"
  rect 0.65x2.75 smd: 1(-0.775,0) 2(0.775,0)
  silkscreen extent -1.1,-1.9 1.1,1.9, body extent -0.9,-1.7 0.9,1.7, height 0.85
0805_HV [mil] "0805 with 30mil clearance between pads"
  rect 50x63 smd: 1(-40,0) 2(40,0)
  silkscreen extent -74,-40 74,40, body extent -43,-29 43,29, height 57
1206 [mm] "1206 from SM-752 data"
  rect 1.3x1.85 smd: 1(-1.45,0) 2(1.45,0)
  silkscreen extent -2.4,-1.21 2.4,1.21, body extent -1.7,-0.9 1.7,0.9, height 1.35
1206_180 [mm] "1206_180"
  rect 1.1x1.6 smd: 1(-1.7,0) 2(1.7,0)
  silkscreen extent -0.9,-1 0.9,1, body extent -1.75,-0.95 1.75,0.95, height 1.8
AssemblyNote [mil] "Assembly Note"
AssemblyNoteLabel [mil] "Assembly Note for PCB Labels"
BAT_1043 [mil] "Keystone"
  round 80 hole 52: 1(-1410.24,0) 2(1410.24,0)
  round 60 hole 136 unplated: MH1(-1086.61,-314.96) MH2(1086.61,314.96)
  round 60 hole 93.5 unplated: MH3(-1410.24,314.96)
  silkscreen extent -1518,-407 1516,406, body extent -1518,-407 1516,406, height 590
CONN_105017-0001 [mm] "Molex Micro USB-B"
  rect 0.4x1.35 smd mask+0.051: 1(-1.3,1.35) 2(-0.65,1.35) 3(0,1.35) 4(0.65,1.35) 5(1.3,1.35)
  oval 1.2x1.9 hole 0.6 slot 1.3 at 90 deg: 6(-3.5,-1.35) 9(3.5,-1.35)
  rect 1.5x1.9 smd: 7(-1,-1.35) 8(1,-1.35)
  round 1.45 hole 0.85: 10(2.5,1.35) 11(-2.5,1.35)
  Component Side region: 3.5,-0.4 2.3,-0.4 2.3,-2.3 3.5,-2.3
  Component Side region: -3.5,-2.3 -2.3,-2.3 -2.3,-0.4 -3.5,-0.4
  silkscreen extent -4.1,-0.2 4.1,1.4, body extent -4.1,-3.93 4.1,1.5, height 2.72
CONN_SBH11-PBPC-D07-ST-BK [mm] "Sullins recommended land pattern"
  rect 1.65x1.65 hole 1.016 mask+0: 1(-7.62,-1.27)
  round 1.65 hole 1.016 mask+0: 2(-7.62,1.27) 3(-5.08,-1.27) 4(-5.08,1.27) 5(-2.54,-1.27) 6(-2.54,1.27) 7(0,-1.27) 8(0,1.27) 9(2.54,-1.27) 10(2.54,1.27) 11(5.08,-1.27) 12(5.08,1.27) 13(7.62,-1.27) 14(7.62,1.27)
  silkscreen extent -12.64,-5.08 12.64,4.7, body extent -12.64,-4.4 12.64,4.7, height 9.12
DCU0008A_N [mm] "TSSOP, 8-Leads, Body 2x2.3mm, Pitch 0.5mm, IPC Medium Density"
  oval 0.8x0.3 smd: 1(-1.6,0.75) 2(-1.6,0.25) 3(-1.6,-0.25) 4(-1.6,-0.75) 5(1.6,-0.75) 6(1.6,-0.25) 7(1.6,0.25) 8(1.6,0.75)
  silkscreen extent -1.05,-1.05 0.38,1.05, body extent -1.56,-1 1.56,1, height 0.9
DQG0008A [mm] "SMD, 8-Leads, Body 3.3x3.3mm, Pitch 0.65mm"
  rrect45% 0.75x0.44 smd paste-0.05 mask-0.05: 1(-1.525,0.975) 2(-1.525,0.325) 3(-1.525,-0.325) 4(-1.525,-0.975) 5(1.525,-0.975) 6(1.525,-0.325) 7(1.525,0.325) 8(1.525,0.975)
  rrect15% 0.676x1.125 on Top Paste: 9(-0.212,-0.663) 9(-0.212,0.662) 9(0.664,-0.663) 9(0.664,0.662)
  rrect6% 1.775x2.45 on Top Solder: 9(0.327,0)
  rrect8% 2.5x2.55 smd paste-1.5 mask-1.5: 9(0.65,0)
  rrect29% 0.5x0.34 on Top Solder: 9(1.175,-0.975) 9(1.175,-0.325) 9(1.175,0.325) 9(1.175,0.975)
  silkscreen extent -1.8,-1.8 1.8,1.8, body extent -1.65,-1.65 1.65,1.65, height 1.1
DRV0006A [mm] "SON, 6-Leads, Body 2x2mm, Pitch 0.65mm, Thermal Pad 1.6x1mm, TI Recommended"
  rrect33% 0.45x0.3 smd: 1(-0.975,0.65) 2(-0.975,0) 3(-0.975,-0.65) 4(0.975,-0.65) 5(0.975,0) 6(0.975,0.65)
  rrect14% 1x0.7 on Top Paste: 7(0,-0.45) 7(0,0.45)
  rrect10% 1x1.6 smd paste-0.5: 7(0,0)
  silkscreen extent -1.05,-1.2 1.05,1.2, body extent -1.05,-1.05 1.05,1.05, height 0.81
DSE0006A [mm] "TI recommended land pattern"
  rect 0.66x0.25 smd: 1(-0.62,0.5)
  rect 0.7x0.25 smd: 2(-0.6,0) 3(-0.6,-0.5) 4(0.6,-0.5) 5(0.6,0) 6(0.6,0.5)
  Component Side region: -0.3,0.625 -0.25,0.625 -0.15,0.525 -0.15,0.375 -0.3,0.375
  silkscreen extent -0.9,-0.92 0.9,0.92, body extent -0.77,-0.77 0.77,0.77, height 0.8
FCC_disclaimer [mil]
Fiducial10-30 [mm]
  round 1 smd mask+1: 1(0,0)
  Component Side keep-out circle w1.678: c0,0 r0.75
IHLP-2020BZ [mm] "Vishay Dale recommended land pattern.  Document 34261 rev 12-Sept-13"
  rect 1.915x2.79 smd: 1(-2.037,0) 2(2.037,0)
  silkscreen extent -2.9,-2.7 2.9,2.7, body extent -2.87,-2.72 2.87,2.72, height 2
JST_B3B-XH-A [mm] "Header (Shrouded), 2.5mm, 3x1, TH"
  rect 1.4x1.4 hole 0.9: 1(-2.5,0)
  round 1.4 hole 0.9: 2(0,0) 3(2.5,0)
  Component Side lines w0.1: 0.32,0.32 0,0 ; 0.32,-0.32 0,0 ; -0.32,0.32 -0.064,0.063 0,0 ; -0.32,-0.32 -0.127,-0.127 -0.063,-0.064 0,0
  silkscreen extent -5.4,-2.38 4.95,3.37, body extent -4.95,-2.38 4.95,3.37, height 7
JST_B4B-XH-A [mm] "Header (Shrouded), 2.5mm, 4x1, TH"
  rect 1.4x1.4 hole 0.9: 1(-3.75,0)
  round 1.4 hole 0.9: 2(-1.25,0) 3(1.25,0) 4(3.75,0)
  silkscreen extent -6.6,-2.38 6.2,3.37, body extent -6.2,-2.38 6.2,3.37, height 7
JST_B5B-XH-A [mm] "Header(shrouded), 2.5mm, 5x1, TH"
  rect 1.4x1.4 hole 0.9: 1(-5,0)
  round 1.4 hole 0.9: 2(-2.5,0) 3(0,0) 4(2.5,0) 5(5,0)
  silkscreen extent -7.45,-2.98 7.45,3.4, body extent -7.45,-2.35 7.45,3.4, height 7.01
JST_B6B-XH-A [mm] "Header (Shrouded), 2.5mm, 6x1, TH"
  rect 1.4x1.4 hole 0.9: 1(-6.25,0)
  round 1.4 hole 0.9: 2(-3.75,0) 3(-1.25,0) 4(1.25,0) 5(3.75,0) 6(6.25,0)
  silkscreen extent -9.25,-2.38 8.7,3.37, body extent -8.7,-2.37 8.7,3.38, height 7.01
Keystone_1902C [mil] "Hex Standoff, 4-40 threaded, nylon"
  body extent -145,-126 146,126, height 501
Label_650x200 [mil] "Thermal Transfer Label"
  silkscreen extent -325,-100 325,100, body extent -325,-100 325,100, height 1
M-FLAT [mm] "Toshiba 3-4E1A recommended land pattern"
  rect 1.4x2.1 smd: 1(-2.2,0) 2(2.2,0)
  silkscreen extent -3.56,-1.47 2.77,1.47, body extent -2.45,-1.3 2.45,1.3, height 1
MUA08A_N [mm] "TSOP, 8-Leads, Body 3x3mm, Pitch 0.65mm, IPC Medium Density"
  oval 1.7x0.45 smd: 1(-2.1,0.975) 2(-2.1,0.325) 3(-2.1,-0.325) 4(-2.1,-0.975) 5(2.1,-0.975) 6(2.1,-0.325) 7(2.1,0.325) 8(2.1,0.975)
  silkscreen extent -2.22,-1.55 0.85,1.87, body extent -1.6,-1.6 1.6,1.6, height 1.09
MUB10A_N [mm] "TSSOP, 10-Leads, Body 3x3mm, Pitch 0.5mm, IPC Medium Density"
  oval 1.7x0.3 smd: 1(-2.05,1) 2(-2.05,0.5) 3(-2.05,0) 4(-2.05,-0.5) 5(-2.05,-1) 6(2.05,-1) 7(2.05,-0.5) 8(2.05,0) 9(2.05,0.5) 10(2.05,1)
  silkscreen extent -2.17,-1.6 0.8,1.82, body extent -1.6,-1.6 1.6,1.6, height 1.09
Net-Tie_10mil [mil] "10mil net tie, no solder mask opening, no solder paste"
  rect 10x10 smd paste-5 mask-5: 1(-10,0) 2(10,0)
  Component Side region: -6,5 6,5 6,-5 -6,-5
"NY PMS 440 0025 PH" [mm] "4-40 nylon screw and mounting hole"
  round 8 hole 3.2: 1(0,0)
  body extent -3.3,-3.3 3.3,3.3, height 2.69
Pb-Free_Overlay_Medium [mil]
  silkscreen extent -95,-95 95,95
PBC03SAAN [mm] "Sullins 100mil, 1x3, 230 mil above insulator"
  rect 1.65x1.65 hole 1.016: 1(-2.54,0)
  round 1.65 hole 1.016: 2(0,0) 3(2.54,0)
  silkscreen extent -3.81,-1.27 3.81,1.27, body extent -3.81,-1.27 3.81,1.27, height 8.38
PHP0048D_N [mm] "Thin QFP, 48-Leads, Body 7x7mm, Pitch 0.5mm, Thermal Pad 4.5x4.5mm, IPC Medium Density"
  rrect100% 1.45x0.3 smd: 1(-4.225,2.75) 2(-4.225,2.25) 3(-4.225,1.75) 4(-4.225,1.25) 5(-4.225,0.75) 6(-4.225,0.25) 7(-4.225,-0.25) 8(-4.225,-0.75) 9(-4.225,-1.25) 10(-4.225,-1.75) 11(-4.225,-2.25) 12(-4.225,-2.75) 25(4.225,-2.75) 26(4.225,-2.25) 27(4.225,-1.75) 28(4.225,-1.25) 29(4.225,-0.75) 30(4.225,-0.25) 31(4.225,0.25) 32(4.225,0.75) 33(4.225,1.25) 34(4.225,1.75) 35(4.225,2.25) 36(4.225,2.75)
  rrect100% 0.3x1.45 smd: 13(-2.75,-4.225) 14(-2.25,-4.225) 15(-1.75,-4.225) 16(-1.25,-4.225) 17(-0.75,-4.225) 18(-0.25,-4.225) 19(0.25,-4.225) 20(0.75,-4.225) 21(1.25,-4.225) 22(1.75,-4.225) 23(2.25,-4.225) 24(2.75,-4.225) 37(2.75,4.225) 38(2.25,4.225) 39(1.75,4.225) 40(1.25,4.225) 41(0.75,4.225) 42(0.25,4.225) 43(-0.25,4.225) 44(-0.75,4.225) 45(-1.25,4.225) 46(-1.75,4.225) 47(-2.25,4.225) 48(-2.75,4.225)
  rrect2% 4.9x4.9 smd: 49(0,0)
  silkscreen extent -4.17,3.33 -3.93,3.58, body extent -4.51,-4.51 4.51,4.51, height 1.2
RHA0040D [mm] "QFN, 40-Leads, Body 6x6mm, Pitch 0.5mm, Thermal Pad 2.9x2.9mm"
  oval 0.6x0.23 smd: 1(-2.9,2.25) 2(-2.9,1.75) 3(-2.9,1.25) 4(-2.9,0.75) 5(-2.9,0.25) 6(-2.9,-0.25) 7(-2.9,-0.75) 8(-2.9,-1.25) 9(-2.9,-1.75) 10(-2.9,-2.25) 21(2.9,-2.25) 22(2.9,-1.75) 23(2.9,-1.25) 24(2.9,-0.75) 25(2.9,-0.25) 26(2.9,0.25) 27(2.9,0.75) 28(2.9,1.25) 29(2.9,1.75) 30(2.9,2.25)
  oval 0.23x0.6 smd: 11(-2.25,-2.9) 12(-1.75,-2.9) 13(-1.25,-2.9) 14(-0.75,-2.9) 15(-0.25,-2.9) 16(0.25,-2.9) 17(0.75,-2.9) 18(1.25,-2.9) 19(1.75,-2.9) 20(2.25,-2.9) 31(2.25,2.9) 32(1.75,2.9) 33(1.25,2.9) 34(0.75,2.9) 35(0.25,2.9) 36(-0.25,2.9) 37(-0.75,2.9) 38(-1.25,2.9) 39(-1.75,2.9) 40(-2.25,2.9)
  rect 2.9x2.9 smd paste-1.45: 41(0,0)
  silkscreen extent -3.18,-3.18 3.18,3.18, body extent -3.07,-3.07 3.07,3.07, height 1.01
RTW0024H [mm] "QFN, 24-Leads, Body 4x4mm, Pitch 0.5mm, Thermal Pad 2.7x2.7mm"
  oval 0.6x0.24 smd: 1(-1.9,1.25) 2(-1.9,0.75) 3(-1.9,0.25) 4(-1.9,-0.25) 5(-1.9,-0.75) 6(-1.9,-1.25) 13(1.9,-1.25) 14(1.9,-0.75) 15(1.9,-0.25) 16(1.9,0.25) 17(1.9,0.75) 18(1.9,1.25)
  oval 0.24x0.6 smd: 7(-1.25,-1.9) 8(-0.75,-1.9) 9(-0.25,-1.9) 10(0.25,-1.9) 11(0.75,-1.9) 12(1.25,-1.9) 19(1.25,1.9) 20(0.75,1.9) 21(0.25,1.9) 22(-0.25,1.9) 23(-0.75,1.9) 24(-1.25,1.9)
  rect 2.7x2.7 smd paste-1.35: 25(0,0)
  silkscreen extent -2.22,-2.22 2.22,2.22, body extent -2.07,-2.07 2.07,2.07, height 1.01
SM_RADIAL_E [mm] "8 x 6.2mm:  Panasonic E"
  rect 4x1.6 smd: 1(-3.1,0) 2(3.1,0)
  silkscreen extent -4.25,-4.25 4.25,4.25, body extent -4.25,-4.25 4.25,4.25, height 6.5
SM_RADIAL_F [mm] "8 x 10.2mm:  Panasonic F"
  rect 4x2 smd: 1(-3.55,0) 2(3.55,0)
  silkscreen extent -4.25,-4.25 4.25,4.25, body extent -4.25,-4.25 4.25,4.25, height 10.5
SMA [mm] "Molded Diode, 2-Leads, Body 4.3x2.6mm, IPC Medium Density, based on OnSemi component dimensions and land pattern"
  rect 2x2 smd: 1(-2,0) 2(2,0)
  silkscreen extent -3.66,-1.57 2.79,1.57, body extent -2.6,-1.3 2.6,1.3, height 2.42
SNT-100-BK-G [mil] "Samtec STEP model"
  round 1 on Mech3: 0(0,0)
  body extent -100,-50 100,50, height 344
SRR1280 [mm] "Bourns UL"
  rect 2.9x5.4 smd: 1(-4.851,0) 2(4.851,0)
  silkscreen extent -6.48,-6.48 6.48,6.48, body extent -6.4,-6.4 6.4,6.4, height 8
SW_FSM4JSMA [mm] "Alcoswitch"
  rect 1.4x2.1 smd: 1(2.25,4.55) 2(2.25,-4.55) 3(-2.25,4.55) 4(-2.25,-4.55)
  silkscreen extent -3,-3 3,5.4, body extent -3,-5 3,5, height 5.1
TI_Stacked_SolderMask_Medium [mil]
  rect 1706x392 smd paste-196 mask-196: 0(0,0)
TRANS_NexFET_Q5A [mm] "TI recommended land pattern (nominal) M0139-01"
  rect 0.75x0.675 smd paste-0.1 mask+0.051: 1(-2.776,1.917) 2(-2.776,0.639) 3(-2.776,-0.639) 4(-2.776,-1.917)
  rect 0.655x0.675 smd paste-0.1 mask+0.051: 5(2.776,-1.917) 6(2.776,-0.639) 7(2.776,0.639) 8(2.776,1.917)
  rect 4.295x4.51 smd paste-2.2 mask+0.051: 9(0.301,0)
  silkscreen extent -3.4,-2.8 3.4,2.8, body extent -3.05,-2.5 3.05,2.5, height 1.11
WP710A10_Blue [mm] "TH, 2-Leads, Dia 3.2mm, Pin Spacing 2.54mm"
  rect 1.4x1.4 hole 0.889: 1(-1.27,0)
  round 1.4 hole 0.889: 2(1.27,0)
  silkscreen extent -1.23,-1.6 1.23,1.6, body extent -1.62,-1.6 1.62,1.6, height 10.5
WURTH_61300111121 [mm] "Header, 2.54 mm, 1x1, TH"
  rect 1.65x1.65 hole 1.15: 1(0,0)
  silkscreen extent -1.27,-1.27 1.27,1.27, body extent -1.27,-1.27 1.27,1.27, height 8.54
YZF0009-C01 [mm] "BGA, 9-Leads, Body 1.6205x1.58mm, Pitch 0.5mm"
  round 0.245 smd paste-0.15: A1(-0.5,0.5) A2(0,0.5) A3(0.5,0.5) B1(-0.5,0) B2(0,0) B3(0.5,0) C1(-0.5,-0.5) C2(0,-0.5) C3(0.5,-0.5)
  silkscreen extent -0.92,-0.9 0.92,0.9, body extent -0.82,-0.8 0.82,0.8, height 0.63

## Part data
BT1: "Battery Holder, Plastic, 18650, TH"
C1: "CAP, CERM, 0.047 µF, 25 V, +/- 10%, X7R, 0402"
C2 C4 C8 C9 C11 C17 C19 C36 C40 C57 C59 C62 C64: "CAP, CERM, 10 µF, 25 V, +/- 10%, X7R, 1206"
C3 C5 C10 C12 C18 C20 C30 C31 C32 C33 C35 C38 C39 C42 C48 C56 C58 C63 C65 C68: "CAP, CERM, 0.1 µF, 25 V, +/- 10%, X7R, 0603"
C6 C7: "CAP, AL, 100 µF, 25 V, +/- 20%, 0.26 ohm, SMD"
C13: "CAP, CERM, 4.7 µF, 10 V, +/- 10%, X7R, 0805"
C14 C15: "CAP, AL, 68 µF, 25 V, +/- 20%, 0.3 ohm, SMD"
C16: "CAP, CERM, 33 µF, 25 V, +/- 20%, X5R, 1206"
C21: "CAP, CERM, 0.047 µF, 50 V, +/- 10%, X7R, 0402"
C22: "CAP, CERM, 2700 pF, 50 V, +/- 10%, X7R, 0402"
C23: "CAP, CERM, 0.47 µF, 16 V, +/- 10%, X7R, 0603"
C24: "CAP, CERM, 0.01 µF, 16 V, +/- 10%, X7R, 0402"
C25: "CAP, CERM, 1 µF, 10 V, +/- 10%, X5R, 0402"
C26 C27: "CAP, CERM, 1 µF, 25 V, +/- 10%, X7R, 0603"
C28: "CAP, CERM, 0.1 µF, 10 V, +/- 10%, X7R, 0402"
C29 C34 C43: "CAP, CERM, 2.2 µF, 16 V, +/- 10%, X5R, 0402"
C37: "CAP, CERM, 4700 pF, 50 V, +/- 10%, X7R, 0402"
C41 C44 C46 C47 C49 C50 C53: "CAP, CERM, 1 µF, 16 V, +/- 10%, X7R, 0603"
C45: "CAP, CERM, 220 pF, 50 V, +/- 5%, C0G/NP0, 0402"
C51 C52 C60 C61: "CAP, CERM, 0.01 µF, 50 V, +/- 10%, X7R, 0603"
C54 C55 C66 C67: "CAP, CERM, 1000 pF, 50 V, +/- 10%, X7R, 0603"
D1 D2 D3 D4 D5: "LED, Blue, TH"
D6: "Diode, Schottky, 30 V, 2 A, M-FLAT"
D7 D8 D9 D10: "Diode, Schottky, 30 V, 1 A, SMA"
FID1 FID2 FID3: "Fiducial mark.  There is nothing to buy or mount."
H1 H2 H3 H4: "Machine Screw, Round, #4-40 x 1/4, Nylon, Philips panhead"
H7 H8 H9 H10: "Standoff, Hex, 0.5\"L #4-40 Nylon"
J1: "Connector, Receptacle, Micro-USB Type B, R/A, Bottom Mount SMT"
J2: "Header(shrouded), 2.5mm, 5x1, Tin, TH"
J3: "Header (shrouded), 100 mil, 7x2, Gold, TH"
J4: "Header, 100mil, 3x1, Gold, TH"
J5: "Header (Shrouded), 2.5mm, 6x1, Tin, TH"
J6: "Header (Shrouded), 2.5mm, 3x1, Tin, TH"
J7: "Header (Shrouded), 2.5mm, 4x1, Tin, TH"
L1: "Inductor, Shielded Drum Core, Powdered Iron, 1 µH, 7 A, 0.0181 ohm, SMD"
L2: "Inductor, Drum Core, Ferrite, 4.7 µH, 8.2 A, 0.0155 ohm, SMD"
L3 L4 L5 L6: "Ferrite Bead, 70 ohm @ 100 MHz, 3 A, 1206"
LBL1: library part THT-14-423-10, "Thermal Transfer Printable Labels, 0.650\" W x 0.200\" H - 10,000 per roll"
Logo1: library part TI_Logo, "Texas Instrument Corporate Signature"
Logo2: library part Pb-Free
Logo3: library part FCC_disclaimer, "FCC_disclaimer"
NT1: "Single point connection between nets."
Q1: "MOSFET, N-CH, 25 V, 60 A, VSON-CLIP-8"
Q2 Q3: "MOSFET, N-CH, 30 V, 25 A, SON 5x6mm"
R1: "RES, 196, 1%, 0.063 W, 0402"
R2: "RES, 41.2 k, 1%, 0.063 W, 0402"
R3: "RES, 45.3 k, 1%, 0.063 W, 0402"
R4: "RES, 5.23 k, 1%, 0.063 W, 0402"
R5: "RES, 6.49 k, 1%, 0.063 W, 0402"
R6: "RES, 2.87 k, 1%, 0.063 W, 0402"
R7: "RES, 61.9 k, 1%, 0.063 W, 0402"
R8: "RES, 100, 1%, 0.063 W, 0402"
R9 R10 R11 R17 R22: "RES, 10.0 k, 1%, 0.063 W, 0402"
R12: "RES, 30.1 k, 1%, 0.063 W, 0402"
R13: "RES, 0.009, 1%, 1 W, 0612"
R14: "RES, 1.00 k, 1%, 0.063 W, 0402"
R15: "RES, 0.01, 1%, 1 W, 0612"
R16: "RES, 221, 1%, 0.063 W, 0402"
R18: "RES, 2.21 k, 1%, 0.063 W, 0402"
R20 R21: "RES, 2.20 k, 1%, 0.063 W, 0402"
R23 R24: "RES, 4.70 k, 1%, 0.1 W, 0402"
R25: "RES, 200 k, 1%, 0.063 W, 0402"
R26 R27: "RES, 0, 5%, 0.1 W, 0603"
R28 R29 R30 R31 R33: "RES, 10.0, 1%, 0.063 W, 0402"
R32: "RES, 47.5 k, 1%, 0.063 W, 0402"
R34: "RES, 3.01, 1%, 0.1 W, 0603"
R35: "RES, 120, 5%, 0.063 W, 0402"
R36: "RES, 120 k, 1%, 0.063 W, 0402"
RT1 RT2: "Thermistor NTC, 10.0k ohm, 1%, 0603"
S1: "Switch, Tactile, SPST-NO, 0.05A, 12V, SMT"
SH-J1: "Shunt, 100mil, Gold plated, Black"
TP-9.5 TP-BAT+ TP-BAT- TP-GND1 TP-GND2 TP-USB: "Header, 2.54 mm, 1x1, Gold, TH"
U1: "I2C Controlled 5A Single Cell Charger with NVDC Power Path Management and MaxChargeTM High Voltage Adapter Support, RTW0024H"
U2: "High Efficiency Low-Side N-Channel Controller for Switching Regulators, 10-pin MSOP"
U3: "Single Output Automotive LDO, 150 mA, Fixed 2.5 V Output, 2.2 to 5.5 V Input, with 1 uA Quiescent Current, 6-pin SON (DRV), -40 to 125 degC, Green (RoHS & no Sb/Br)"
U4: "System-Side Impedance Track Fuel Gauge, YZF0009-C01"
U5: "Cost-Effective Voltage and Current Protection Integrated Circuit for Single-Cell Li-Ion and Li-Polymer Batteries , DSE0006A"
U6: "24 MHz Mixed Signal Microcontroller, 1024 B SRAM and 33 GPIOs, -40 to 85 degC, 40-pin QFN (RHA), Green (RoHS & no Sb/Br)"
U7: "8-Bit Micro Power Digital-to-Analog Converter with an I2C-Compatible Interface and External Reference, 8-pin Mini SOIC, Pb-Free"
U8: "Dual Bi-Directional I2C-Bus and SMBus Voltage Level-Translator, 0 to 5.5 V, -40 to 85 degC, 8-pin US8 (DCU), Green (RoHS & no Sb/Br)"
U9: "12-W STEREO CLASS-D AUDIO POWER AMPLIFIER WITH DC VOLUME CONTROL , PHP0048D"
ZZ1: library part AssemblyNoteLabel
ZZ2 ZZ3 ZZ4: library part AssemblyNote

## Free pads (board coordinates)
  round 18 hole 8: 3(125,500) 3(210,2120) 3(210,2145) 3(242,2510) 3(275,2025) 3(315,2025) 3(343,2555) 3(371,2570) 3(385,2120) 3(390,1890) 3(400,2690) 3(410,2145) 3(425,2330) 3(440,1890) 3(445,2090) 3(450,125) 3(455,2030) 3(460,2690) 3(470,1150) 3(480,1300) 3(485,940) 3(505,1985) 3(505,2010) 3(510,1775) 3(530,1985) 3(530,2010) 3(550,470) 3(555,1775) 3(555,1985) 3(555,2010) 3(560,2590) 3(560,2620) 3(580,1985) 3(580,2010) 3(590,2590) 3(590,2620) 3(607,2205) 3(610,1840) 3(610,1990) 3(615,935) 3(620,2590) 3(620,2620) 3(630,2220) 3(640,2365) 3(650,2590) 3(650,2620) 3(653,2207) 3(680,1840) 3(680,2590) 3(680,2620) 3(683,1493) 3(700,2000) 3(707,1510) 3(730,1240) 3(730,1380) 3(739,2177) 3(750,2355) 3(755,1380) 3(777,2355) 3(795,2155) 3(805,1165) 3(820,1595) 3(820,1620) 3(840,805) 3(845,1595) 3(845,1620) 3(870,1595) 3(870,1620) 3(895,1595) 3(895,1620) 3(910,470) 3(915,1360) 3(920,1595) 3(920,1620) 3(940,1213.88) 3(940,1360) 3(945,1595) 3(945,1620) 3(970,1595) 3(970,1620) 3(970,2161) 3(980,2230) 3(980,2270) 3(980,2306) 3(995,1595) 3(995,1620) 3(1010,3095) 3(1020,565) 3(1020,845) 3(1025,1110) 3(1040,1780) 3(1040,1805) 3(1040,1830) 3(1040,1855) 3(1040,1880) 3(1040,1905) 3(1060,935) 3(1065,1780) 3(1065,1805) 3(1065,1830) 3(1065,1855) 3(1065,1880) 3(1065,1905) 3(1103,800) 3(1103,837) 3(1135,755) 3(1175,2650) 3(1203,931) 3(1220,1110) 3(1280,1715) 3(1292,792) 3(1320,1105) 3(1325,125) 3(1333,787) 3(1340,1130) 3(1360,1150) 3(1375,2025.2) 3(1375.2,1965) 3(1380,1170) 3(1391,810) 3(1400,595) 3(1400,745) 3(1411,794) 3(1423,1656) 3(1431,1621) 3(1440,665) 3(1440,1115) 3(1450,535) 3(1455,1403) 3(1475,1730) 3(1495,970) 3(1495,1030) 3(1500,860) 3(1515,915) 3(1520,1125) 3(1520,1150) 3(1520,1175) 3(1520,1200) 3(1525,940) 3(1525,970) 3(1540,535) 3(1545,1827) 3(1580,795) 3(1580,901) 3(1617,1806) 3(1651,626) 3(1685,1070) 3(1700,760) 3(1730,535) 3(1740,1568) 3(1755,830) 3(1755,870) 3(1805,1690) 3(1820.98,1877.17) 3(1837,1636) 3(1890,945) 3(1985,1920) 3(1985,1975) 3(2010,2244) 3(2075,1135) 3(2075,1615) 3(2086,944) 3(2170,925) 3(2170,950) 3(2170,1790) 3(2170,1815) 3(2245,2765) 3(2288,1867) 3(2318,1080) 3(2319,3097) 3(2330,1658) 3(2335,2765) 3(2340,1080) 3(2345,1290) 3(2345,1450) 3(2355,1658) 3(2365,1868) 3(2370,1290) 3(2370,1450) 3(2395,1290) 3(2395,1450) 3(2400,1149) 3(2405,1605) 3(2420,1150) 3(2420,1290) 3(2420,1450) 3(2424,1370) 3(2430,960) 3(2430,1605) 3(2449,1370) 3(2480,1005) 3(2520,1005) 3(2550,525) 3(2560,1585) 3(2565,990) 3(2575,125) 3(2577,1161) 3(2582,1091) 3(2615,985) 3(2630,1750) 3(2664,1846) 3(2675,980) 3(2704,1129) 3(2710,1846) 3(2720,1750) 3(2728,1129) 3(2760,915) 3(2798,1753) 3(2832,1753) 3(2835,1005) 3(2870,1754) 3(2890,965) 3(2894,1371) 3(2905,1150) 3(2905,1290) 3(2905,1595) 3(2910,1450) 3(2918,1371) 3(2925,1145) 3(2930,1290) 3(2935,1450) 3(2955,1290) 3(2955,1660) 3(2960,1450) 3(2980,1085) 3(2980,1290) 3(2980,1660) 3(2985,1450) 3(3005,1085) 3(3005,1660) 3(3155,940) 3(3155,965) 3(3155,1780) 3(3155,1805) 3(3220,1965) 3(3250,1135) 3(3250,1615) 3(3485,2155) 3(3485,2185) 3(3485,2220) 3(3485,2250) 3(3485,2280) 3(3515,2155) 3(3515,2185) 3(3515,2220) 3(3515,2250) 3(3515,2280) 3(3545,2155) 3(3545,2185) 3(3545,2220) 3(3545,2250) 3(3545,2280) 3(3565,1295) 3(3615,1565) 3(3615,1590) 3(3615,1615) 3(3615,1640) 3(3615,1665) 3(3615,1690) 3(3620,1245) 3(3640,1565) 3(3640,1590) 3(3640,1615) 3(3640,1640) 3(3640,1665) 3(3640,1690) 3(3656,3097) 3(3675,1345) 3(3695,1800) 3(3695,1825) 3(3695,1850) 3(3695,1875) 3(3695,1900) 3(3710,1970) 3(3710,2050) 3(3710,2380) 3(3715,485) 3(3715,675) 3(3735,1055) 3(3795,1400) 3(3800,1245) 3(3815,1800) 3(3815,1825) 3(3815,1850) 3(3815,1875) 3(3815,1900) 3(3830,2050) 3(3830,2380) 3(3880,2170) 3(3905,620) 3(3970,2170) 3(4010,605) 3(4055,1800) 3(4055,1825) 3(4055,1850) 3(4055,1875) 3(4055,1900) 3(4060,2170) 3(4075,1265) 3(4125,1045) 3(4160,1970) 3(4160,2050) 3(4160,2220) 3(4160,2380) 3(4165,480) 3(4165,500) 3(4165,520) 3(4165,540) 3(4175,1800) 3(4175,1825) 3(4175,1850) 3(4175,1875) 3(4175,1900) 3(4180,1225) 3(4210,1120) 3(4215,1320) 3(4220,640) 3(4255,640) 3(4260,1120) 3(4280,1010) 3(4280,1035) 3(4280,1060) 3(4280,1085) 3(4280,2050) 3(4280,2220) 3(4280,2380) 3(4300,480) 3(4300,500) 3(4300,520) 3(4300,540) 3(4305,1010) 3(4305,1035) 3(4305,1060) 3(4305,1085) 3(4465,1880) 3(4505,1880) 3(4530,480) 3(4530,500) 3(4530,520) 3(4530,540) 3(4550,250) 3(4580,640) 3(4585,1825) 3(4600,1970) 3(4615,640) 3(4665,480) 3(4665,500) 3(4665,520) 3(4665,540) 3(4825,600) 3(4825,1450) 3(4825,2750)
  round 14 hole 6: 4(430,2534)

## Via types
v1: diameter 19.68, hole 7.87, Component Side to Solder Side, 43 vias
v2: diameter 19.68, hole 7.87, Component Side to Solder Side, tented both sides, 1 vias

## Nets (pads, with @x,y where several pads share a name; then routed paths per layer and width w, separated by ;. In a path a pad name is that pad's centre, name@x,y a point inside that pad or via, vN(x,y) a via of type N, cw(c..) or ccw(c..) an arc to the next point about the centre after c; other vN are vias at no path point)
5V: C2.1 C3.1 J1.1 TP-USB.1 U1.1 | length 886.6
  Component Side w12: J1.1@163.15,2171.18 C2.1@286.18,2171.18 ; C2.1@290,2175 C2.1@286.18,2171.18 ; C2.1@296.18,2171.18 C2.1@286.18,2171.18 ; U1.1@709.21,2174.8 709.21,2199.21
  Component Side w25: TP-USB.1@216.48,2370 294,2292.48 C2.1@294,2178 ; C2.1@320,2195 345,2195 439,2289 C3.1@681,2289 ; C3.1@681,2287 681.43,2287 709.21,2259.21 709.21,2230.28 ; 709.21,2199.21 709.21,2200.04 709.21,2230.27
A-GND: C30.2 C31.2 C33.2 C42.2 C43.2 C44.2 C48.2 NT1.2 pad.3@1375,2025.2 pad.3@1375.2,1965 pad.3@1805,1690 pad.3@1820.98,1877.17 pad.3@1985,1920 pad.3@1985,1975 pad.3@2560,1585 pad.3@2565,990 pad.3@2577,1161 pad.3@2615,985 pad.3@2630,1750 pad.3@2720,1750 R26.1 R27.1 U7.5 U9.12 U9.26 | length 658.4
  Component Side w10: pad.3@1375.2,1965 R27.1@1433.5,1965 ; pad.3@1375.2,2025 R26.1@1433.5,2025 ; C33.2@1751.5,1690 pad.3@1805,1690 ; U7.5@1777.68,1911.61 1814.37,1911.61 1820.98,1905 pad.3@1820.98,1877.17 ; C30.2@1936.5,1920 pad.3@1985,1920 ; C31.2@1936.5,1975 pad.3@1985,1975 ; 2557,1005 C43.2@2557,1043.38 ; U9.12@2561.1,1536.97 pad.3@2561.1,1583.9 ; pad.3@2577,1161 2580.79,1164.79 U9.26@2580.79,1204.29 ; U9.26@2580,1200 NT1.2@2580,1245 ; pad.3@2613,979 C42.2@2613,1023.5 ; C48.2@2629.37,1702.13 pad.3@2629.37,1751.37 ; C44.2@2719.37,1702.13 pad.3@2719.37,1750.63
AVDD_5V: C30.1 C42.1 C43.1 pad.3@1837,1636 pad.3@2582,1091 R23.2 R24.2 R25.1 U7.6 U9.29 | length 2148.2
  Component Side w10: R25.1@1733.62,1745 1763.19,1745 1775,1756.81 1775,1760 ; R23.2@1733.62,1805 1770,1805 1775,1810 ; R24.2@1733.62,1850 1775,1850 ; U7.6@1777.68,1937.2 1822.8,1937.2 1840,1920 C30.1@1873.5,1920 1873.5,1865 1858.5,1850 1775,1850 ; pad.3@1835,1635 1850,1650 1850,1730 1820,1760 1775,1760 ; C43.1@2558,1090 2609.5,1090 C42.1@2613,1086.5 ; C42.1@2615,1083 2615,1116 2619,1120 2631,1120 2639.84,1128.84 U9.29@2639.84,1204.29 ; 1775,1760 1775,1810 ; 1775,1810 1775,1850
  Solder Side w10: pad.3@1837,1635 1842,1640 2279,1640 2286.5,1632.5 2469.5,1632.5 2487,1615 2487,1099 2496,1090 2581,1090 pad.3@2582,1091
CE: pad.3@707,1510 pad.3@1525,940 U1.9 U6.34 | length 2278.2
  Component Side w8: U1.9@585.2,2109.84 569.16,2109.84 557,2122 443,2122 412,2091 412,2033 391,2012 368,2012 361,2005 361,1855 pad.3@707,1509 ; U6.34@1464.17,930.47 U6.34@1465,930.47 ; U6.34@1465,930 1490,930 1494,934 1509.22,934 1515.22,940 pad.3@1525,940
  Solder Side w8: pad.3@705,1510 705,1340 754.15,1290.85 754.15,1179.69 1031.84,902 1300,902 1303,899 1303.28,899 1312.28,890 1432,890 1482,940 pad.3@1525,940
D+: J1.3 pad.3@210,2120 pad.3@385,2120 U1.2 | length 665.8
  Component Side w8: J1.3@163.15,2120 pad.3@210,2120 ; pad.3@385,2120 385,2150 400,2165 489,2165 580,2256 662.8,2256 686.71,2232.09 686.71,2220.96 686.71,2209.36 686.71,2189.89 689.53,2187.08 U1.2@689.53,2174.8
  Signal Layer 2 w8: pad.3@210,2120 pad.3@385,2120
D-: J1.2 pad.3@210,2145 pad.3@410,2145 U1.3 | length 609.1
  Component Side w8: J1.2@163.15,2145.59 pad.3@209.41,2145.59 ; pad.3@410,2145 426.4,2145 431.4,2150 498,2150 590,2242 657,2242 672.71,2226.29 672.71,2192.71 670,2190 U1.3@670,2174
  Signal Layer 2 w8: pad.3@210,2145 pad.3@410,2145
DSEL: pad.3@739,2177 pad.3@1103,837 pad.3@1292,792 R10.1 U1.24 U6.22 | length 2510.8
  Component Side w8: U1.24@734.8,2149.21 734.8,2171.8 pad.3@739,2176
  Component Side w10: U6.22@1281.1,845.83 1281.1,803.9 1310,775 R10.1@1310,725
  Signal Layer 2 w8: pad.3@740,2175 670,2245 670,2313.79 741.21,2385 983.79,2385 1145,2223.79 1145,1166 1103,1124 pad.3@1103,837
  Solder Side w8: pad.3@1103,837 1173,837 1217,793 pad.3@1291,793
GPOUT: R17.1 U4.A1 | length 77.1
  Component Side w8: R17.1@335,2510 365,2510 369.32,2514.32 U4.A1@410.32,2514.32
INT: pad.3@683,1493 pad.3@1333,787 R9.1 U1.7 U6.23 | length 2299.6
  Component Side w8: U1.7@585.2,2149.21 561.21,2149.21 548,2136 437.2,2136 398,2096.8 398,2038.8 385.2,2026 362.2,2026 347,2010.8 347,1849.2 682.6,1513.6 pad.3@682.6,1492.4
  Component Side w10: U6.23@1300.79,845.83 1300.79,819.21 pad.3@1333,787 1360,760 R9.1@1360,725
  Solder Side w8: pad.3@683,1493 683,1139 1046,776 1191,776 1200,767 1314,767 pad.3@1334,787
LSPKR+: C55.1 J7.3 L5.1 | length 1431.2
  Component Side w25: C55.1@2075,1241.5 2075,1325 ; 2077.91,1325 2075,1325 ; L5.1@2145,1325 2075,1325 ; 2160,815 2650,815 2680,785 J7.3@2680,695 ; 2160,820 1975,1005 1975,1275 2025,1325 2075,1325
LSPKR-: C54.1 J7.4 L3.1 | length 1505.8
  Component Side w25: C54.1@2077.91,1502.09 2077.91,1420 ; 2130,760 2565,760 2580,745 J7.4@2580,695 ; 2130,765 1910,985 1910,1320 2010,1420 2077.91,1420 ; L3.1@2140,1420 2077.91,1420
NetBT1_1: BT1.1 C25.1 R15.2 R16.2 TP-BAT+.1 U4.C1 U4.C3 | length 3124.8
  Component Side w8: U4.C3@449.68,2553.68 460,2564 460,2575 ; U4.C1@451,2515 615,2515 620,2510 620,2475 ; C25.1@460,2610 C25.1@460,2606.38 460,2575 ; 535,2675 515,2675 500,2660 500,2590 485,2575 460,2575 ; 985,2880 2540,2880 2590,2830 2590,2705 3180,2115 3254.76,2115 3264.88,2104.88 R16.2@3264.88,2078.37
NetBT1_2: BT1.2 C28.2 Q3.1 Q3.2 Q3.3 TP-BAT-.1 U5.4 | length 698.8
  Component Side w10: C28.2@3315,2080 3350,2080 ; U5.4@3401.26,2064.43 3365.57,2064.43 3350,2080 ; 3570,2510 3570,2350 3560,2340 3450,2340 3430,2320 3430,2125 3415,2110 3380,2110 3350,2080
NetC1_1: C1.1 L1.1 U1.19 U1.20 | length 28.6
  Component Side w10: 880,2066.38 C1.1@880,2095
NetC1_2: C1.2 U1.21 | length 90
  Component Side w10: U1.21@734.96,2090 C1.2@825,2090
NetC4_1: C4.1 C5.1 U1.23 | length 148.9
  Component Side w10: U1.23@734.8,2129.53 754.53,2129.53 760,2135
  Component Side w20: C5.1@750,2243.5 760,2233.5 C5.1@765,2228.5 ; 760,2130.84 760.84,2130.84 765,2135
  Component Side w25: 767,2137 C5.1@767,2230.5
NetC6_1: C6.1 C7.1 C8.1 C9.1 C10.1 C11.1 C12.1 C26.1 L1.2 L2.1 pad.3@940,1213.88 pad.3@1040,1780 pad.3@1040,1805 pad.3@1040,1830 pad.3@1040,1855 pad.3@1040,1880 pad.3@1040,1905 pad.3@1065,1780 pad.3@1065,1805 pad.3@1065,1830 pad.3@1065,1855 pad.3@1065,1880 pad.3@1065,1905 pad.3@3615,1565 pad.3@3615,1590 pad.3@3615,1615 pad.3@3615,1640 pad.3@3615,1665 pad.3@3615,1690 pad.3@3640,1565 pad.3@3640,1590 pad.3@3640,1615 pad.3@3640,1640 pad.3@3640,1665 pad.3@3640,1690 R2.2 U1.15 U1.16 U2.10 U3.4 U3.6 | length 1126
  Component Side w10: U3.4@878.39,1189.41 899.41,1189.41 910,1200 910,1213.88 910,1227.75 897.16,1240.59 U3.6@878.39,1240.59 ; R2.2@3995,1400 4045,1400 ; U2.10@4015.71,1324.37 4054.37,1324.37 4060,1330 4060,1385 4045,1400 ; 4060,1530 4060,1415 4045,1400
  Component Side w20: 910,1213.88 pad.3@940,1213.88 C26.1@940,1253.5
  Signal Layer 2 w20: pad.3@940,1213.88 1006.79,1213.88 1040,1247.09 pad.3@1040,1780
NetC13_1: C13.1 pad.3@440,1890 pad.3@795,2155 R4.2 U1.22 | length 772.7
  Component Side w10: pad.3@440,1890 R4.2@440,1931.38 ; U1.22@734.8,2109.84 784.84,2109.84 795,2120 pad.3@795,2155 800,2160 C13.1@840,2160
  Signal Layer 2 w10: pad.3@440,1890 735,1890 795,1950 pad.3@795,2155
NetC19_1: C19.1 C20.1 pad.3@505,1985 pad.3@505,2010 pad.3@530,1985 pad.3@530,2010 pad.3@555,1985 pad.3@555,2010 pad.3@560,2590 pad.3@560,2620 pad.3@580,1985 pad.3@580,2010 pad.3@590,2590 pad.3@590,2620 pad.3@610,1990 pad.3@620,2590 pad.3@620,2620 pad.3@650,2590 pad.3@650,2620 pad.3@680,2590 pad.3@680,2620 R15.1 U1.13 U1.14 U4.C2 | length 223.7
  Component Side w8: U4.C2@449,2535 616,2535 620,2539 pad.3@620,2590
NetC21_1: C21.1 C22.1 U2.3 | length 185.9
  Component Side w10: C22.1@3708.62,1245 3740,1245 3765,1270 3765,1295 3795,1295 3805,1285 U2.3@3854.29,1285 U2.3@3855,1285
NetC21_2: C21.2 R6.2 | length 61.4
  Component Side w10: R6.2@3653.62,1295 C21.2@3715,1295
NetC23_1: C23.1 U2.9 | length 95.6
  Component Side w10: U2.9@4015.71,1304.69 4059.69,1304.69 4075,1320 C23.1@4103.5,1320 C23.1@4105,1320
NetC24_1: C24.1 R8.1 U2.1 | length 494.7
  Component Side w10: C24.1@3765,1345 3790,1345 3799,1336 3801.63,1336 3812.63,1325 U2.1@3853.66,1325 ; U2.1@3860,1325 3905,1325 3915,1315 3915,1210 4005,1120 R8.1@4111.38,1120
NetC28_1: C28.1 R16.1 U5.5 | length 207.6
  Component Side w10: R16.1@3265,2030 3265,2000 3270,1995 3310,1995 3314.88,1999.88 C28.1@3314.88,2031.12 ; C28.1@3315,2030 3350,2030 3364.74,2044.74 U5.5@3401.26,2044.74
NetC29_1: C29.1 U4.B3 | length 75.5
  Component Side w8: C29.1@400,2605 400,2580 405,2575 425,2575 430,2570 U4.B3@430,2553.68
NetC31_1: C31.1 C48.1 pad.3@2288,1867 pad.3@2365,1868 U7.7 U9.7 U9.8 U9.9 U9.10 | length 1359.3
  Component Side w10: U7.7@1777.68,1962.8 1822.8,1962.8 1835,1975 C31.1@1873.5,1975 1873.5,2011.5 1881,2019 2138,2019 pad.3@2288,1867 ; pad.3@2365,1868 2596,1640 2628.5,1640 C48.1@2629.37,1639.13 ; U9.10@2600,1535 2600,1585 2630,1585 ; U9.9@2620.16,1536.97 2620.16,1579.84 ; C48.1@2630,1640 2630,1585 ; U9.8@2639.84,1536.97 2639.84,1584.84 ; U9.7@2659.53,1536.97 2659.53,1584.53 2659.06,1585 2630,1585
  Signal Layer 2 w10: pad.3@2288,1867 2366,1867 pad.3@2367,1868
NetC33_1: C33.1 R25.2 U8.7 U8.8 | length 151.3
  Component Side w8: U8.7@1602.99,1684.84 1629.84,1684.84 1635,1690 ; 1630.47,1704.53 1635,1700 1635,1690 ; C33.1@1688.5,1690 1635,1690
  Component Side w10: U8.8@1602.99,1704.53 1630.47,1704.53 1649.53,1704.53 1650,1705
NetC37_1: C37.1 U6.30 | length 89.4
  Component Side w10: C37.1@1438.58,756.42 U6.30@1438.58,845.83
NetC38_1: C38.1 R34.1 U6.40 | length 186.8
  Component Side w10: U6.40@1464.17,1048.58 1473.58,1048.58 1495,1070 1570,1070 1575,1065 R34.1@1575,1001.5 R34.1@1575,1000
NetC41_2: C41.2 U9.25 | length 230.6
  Component Side w10: C41.2@2430,1060 2430,1061.5 2430,1097 2495,1162 2549.72,1162 2561.1,1173.39 U9.25@2561.1,1204.29
NetC44_1: C44.1 U9.4 | length 106.3
  Component Side w10: C44.1@2718,1643 2718.58,1642.42 U9.4@2718.58,1536.97
NetC45_1: C45.1 U9.28 | length 195.6
  Component Side w10: C45.1@2520,1090 2520,1113 2530,1123 2598,1123 2620.16,1145.16 U9.28@2620.16,1204.29
NetC46_1: C46.1 pad.3@1730,535 pad.3@2832,1753 U9.2 | length 2453.7
  Component Side w10: U9.2@2757.95,1536.97 2757.95,1586.33 2785,1613.37 2785,1707 pad.3@2832,1754
  Component Side w12: C46.1@1730,481.5 pad.3@1730,535
  Signal Layer 2 w12: pad.3@1730,535 1730,558 2007,835 2007,836.54 2011,840.54 2011,1661 2054,1704 2284,1704 2366,1786 2727,1786 2788,1725 2803,1725 pad.3@2832,1754
NetC47_1: C47.1 pad.3@1540,535 pad.3@2798,1753 U9.3 | length 2604.1
  Component Side w10: U9.3@2738.27,1536.97 2738.27,1589.27 2769,1620 2769,1723 pad.3@2799,1753
  Component Side w12: C47.1@1540,481.5 pad.3@1540,535
  Signal Layer 2 w12: pad.3@1540,535 1540,576 1566,602 1747,602 1993,848 1993,1668.46 2046.54,1722 2271,1722 2353,1804 2734.46,1804 2785.46,1753 pad.3@2798,1753
NetC47_2: C47.2 J6.2 | length 198.9
  Component Side w12: C47.2@1540,418.5 1540,335 1565,310 1565,235 J6.2@1565,230
NetC49_2: C49.2 U9.36 | length 203.1
  Component Side w10: U9.36@2777.64,1204.29 2777.64,1174.36 2806,1146 2844,1146 2890,1100 C49.2@2890,1071.5 C49.2@2890,1070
